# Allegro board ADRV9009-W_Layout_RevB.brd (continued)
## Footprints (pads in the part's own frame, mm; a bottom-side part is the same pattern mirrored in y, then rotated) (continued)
C0201
  rect 0.305x0.406 smd: 1(-0.318,0) 2(0.318,0)
C0402
  rect 0.61x0.61 smd: 1(-0.495,0) 2(0.495,0)
C0402#2
  rect 0.483x0.559 smd: 1(-0.438,0) 2(0.438,0)
C0603
  rect 1.092x1.194 smd: 1(-0.851,0) 2(0.851,0)
C0603#2
  rect 0.762x0.889 smd: 1(-0.7,0) 2(0.7,0)
C0805H53
  rect 1.295x1.6 smd: 1(-0.953,0) 2(0.953,0)
C0805H60
  rect 1.295x1.6 smd: 1(-0.953,0) 2(0.953,0)
C1210
  rect 1.575x2.692 smd: 1(-1.397,0) 2(1.397,0)
C1210-2
  rect 1.575x2.692 smd: 1(-1.397,0) 2(1.397,0)
C1210-2#2
  rect 1.092x2.057 smd: 1(-1.646,0) 2(1.646,0)
CNAMPHENOL132255-11
  rect 2.54x0.432 smd: 1(-0.508,0)
  rect 6.35x1.524 hole 0.508: 2(-2.413,4.25) 4(-2.413,-4.25)
  round 0.305 smd: 3(-2.413,4.25) 5(-2.413,-4.25)
CNBERG1X3H205LD36
  rect 1.651x1.651 hole 1.143: 1(0,0)
  round 1.651 hole 1.143: 2(2.54,0) 3(5.08,0)
CNBERG2X10H330LD36
  rect 1.651x1.651 hole 1.143: 1(0,0)
  round 1.651 hole 1.143: 2(0,2.54) 3(2.54,0) 4(2.54,2.54) 5(5.08,0) 6(5.08,2.54) 7(7.62,0) 8(7.62,2.54) 9(10.16,0) 10(10.16,2.54) 11(12.7,0) 12(12.7,2.54) 13(15.24,0) 14(15.24,2.54) 15(17.78,0) 16(17.78,2.54) 17(20.32,0) 18(20.32,2.54) 19(22.86,0) 20(22.86,2.54)
CNHDR2X10H251
  rect 0.737x2.794 smd: 1(-5.715,-2.032) 2(-5.715,2.032) 3(-4.445,-2.032) 4(-4.445,2.032) 5(-3.175,-2.032) 6(-3.175,2.032) 7(-1.905,-2.032) 8(-1.905,2.032) 9(-0.635,-2.032) 10(-0.635,2.032) 11(0.635,-2.032) 12(0.635,2.032) 13(1.905,-2.032) 14(1.905,2.032) 15(3.175,-2.032) 16(3.175,2.032) 17(4.445,-2.032) 18(4.445,2.032) 19(5.715,-2.032) 20(5.715,2.032)
CNHIROSE-U_FL-R-SMT-1
  rect 0.991x1.041 smd: 1(0,-1.521)
  rect 1.041x2.21 smd: 2(-1.471,0) 3(1.471,0)
CNJOHNSON142-0701-201
  round 2.032 hole 1.524: 1(0,0) 2(-2.54,2.54) 3(2.54,2.54) 4(2.54,-2.54) 5(-2.54,-2.54)
CNKEY5001TP
  round 1.524 hole 1.016: 1(0,0)
CNSAMTEC1X2H330LD36
  rect 1.651x1.651 hole 1.143: 1(-1.27,0)
  round 1.651 hole 1.143: 2(1.27,0)
CNSAMTEC2X5H338LD36
  rect 1.651x1.651 hole 1.143: 1(0,0)
  round 1.651 hole 1.143: 2(0,2.54) 3(2.54,0) 4(2.54,2.54) 5(5.08,0) 6(5.08,2.54) 7(7.62,0) 8(7.62,2.54) 9(10.16,0) 10(10.16,2.54)
CNSAMTECASP-134488-01
  round 2.54 hole 1.27 unplated: (-2.426,5.715) (51.956,8.763)
  round 0.889 smd: A1(0,0) A2(1.27,0) A3(2.54,0) A4(3.81,0) A5(5.08,0) A6(6.35,0) A7(7.62,0) A8(8.89,0) A9(10.16,0) A10(11.43,0) A11(12.7,0) A12(13.97,0) A13(15.24,0) A14(16.51,0) A15(17.78,0) A16(19.05,0) A17(20.32,0) A18(21.59,0) A19(22.86,0) A20(24.13,0) A21(25.4,0) A22(26.67,0) A23(27.94,0) A24(29.21,0) A25(30.48,0) A26(31.75,0) A27(33.02,0) A28(34.29,0) A29(35.56,0) A30(36.83,0) A31(38.1,0) A32(39.37,0) A33(40.64,0) A34(41.91,0) A35(43.18,0) A36(44.45,0) A37(45.72,0) A38(46.99,0) A39(48.26,0) A40(49.53,0) B1(0,1.27) B2(1.27,1.27) B3(2.54,1.27) B4(3.81,1.27) B5(5.08,1.27) B6(6.35,1.27) B7(7.62,1.27) B8(8.89,1.27) B9(10.16,1.27) B10(11.43,1.27) B11(12.7,1.27) B12(13.97,1.27) B13(15.24,1.27) B14(16.51,1.27) B15(17.78,1.27) B16(19.05,1.27) B17(20.32,1.27) B18(21.59,1.27) B19(22.86,1.27) B20(24.13,1.27) B21(25.4,1.27) B22(26.67,1.27) B23(27.94,1.27) B24(29.21,1.27) B25(30.48,1.27) B26(31.75,1.27) B27(33.02,1.27) B28(34.29,1.27) B29(35.56,1.27) B30(36.83,1.27) B31(38.1,1.27) B32(39.37,1.27) B33(40.64,1.27) B34(41.91,1.27) B35(43.18,1.27) B36(44.45,1.27) B37(45.72,1.27) B38(46.99,1.27) B39(48.26,1.27) B40(49.53,1.27) C1(0,2.54) C2(1.27,2.54) C3(2.54,2.54) C4(3.81,2.54) C5(5.08,2.54) C6(6.35,2.54) C7(7.62,2.54) C8(8.89,2.54) C9(10.16,2.54) C10(11.43,2.54) C11(12.7,2.54) C12(13.97,2.54) C13(15.24,2.54) C14(16.51,2.54) C15(17.78,2.54) C16(19.05,2.54) C17(20.32,2.54) C18(21.59,2.54) C19(22.86,2.54) C20(24.13,2.54) C21(25.4,2.54) C22(26.67,2.54) C23(27.94,2.54) C24(29.21,2.54) C25(30.48,2.54) C26(31.75,2.54) C27(33.02,2.54) C28(34.29,2.54) C29(35.56,2.54) C30(36.83,2.54) C31(38.1,2.54) C32(39.37,2.54) C33(40.64,2.54) C34(41.91,2.54) C35(43.18,2.54) C36(44.45,2.54) C37(45.72,2.54) C38(46.99,2.54) C39(48.26,2.54) C40(49.53,2.54) D1(0,3.81) D2(1.27,3.81) D3(2.54,3.81) D4(3.81,3.81) D5(5.08,3.81) D6(6.35,3.81) D7(7.62,3.81) D8(8.89,3.81) D9(10.16,3.81) D10(11.43,3.81) D11(12.7,3.81) D12(13.97,3.81) D13(15.24,3.81) D14(16.51,3.81) D15(17.78,3.81) D16(19.05,3.81) D17(20.32,3.81) D18(21.59,3.81) D19(22.86,3.81) D20(24.13,3.81) D21(25.4,3.81) D22(26.67,3.81) D23(27.94,3.81) D24(29.21,3.81) D25(30.48,3.81) D26(31.75,3.81) D27(33.02,3.81) D28(34.29,3.81) D29(35.56,3.81) D30(36.83,3.81) D31(38.1,3.81) D32(39.37,3.81) D33(40.64,3.81) D34(41.91,3.81) D35(43.18,3.81) D36(44.45,3.81) D37(45.72,3.81) D38(46.99,3.81) D39(48.26,3.81) D40(49.53,3.81) E1(0,5.08) E2(1.27,5.08) E3(2.54,5.08) E4(3.81,5.08) E5(5.08,5.08) E6(6.35,5.08) E7(7.62,5.08) E8(8.89,5.08) E9(10.16,5.08) E10(11.43,5.08) E11(12.7,5.08) E12(13.97,5.08) E13(15.24,5.08) E14(16.51,5.08) E15(17.78,5.08) E16(19.05,5.08) E17(20.32,5.08) E18(21.59,5.08) E19(22.86,5.08) E20(24.13,5.08) E21(25.4,5.08) E22(26.67,5.08) E23(27.94,5.08) E24(29.21,5.08) E25(30.48,5.08) E26(31.75,5.08) E27(33.02,5.08) E28(34.29,5.08) E29(35.56,5.08) E30(36.83,5.08) E31(38.1,5.08) E32(39.37,5.08) E33(40.64,5.08) E34(41.91,5.08) E35(43.18,5.08) E36(44.45,5.08) E37(45.72,5.08) E38(46.99,5.08) E39(48.26,5.08) E40(49.53,5.08) F1(0,6.35) F2(1.27,6.35) F3(2.54,6.35) F4(3.81,6.35) F5(5.08,6.35) F6(6.35,6.35) F7(7.62,6.35) F8(8.89,6.35) F9(10.16,6.35) F10(11.43,6.35) F11(12.7,6.35) F12(13.97,6.35) F13(15.24,6.35) F14(16.51,6.35) F15(17.78,6.35) F16(19.05,6.35) F17(20.32,6.35) F18(21.59,6.35) F19(22.86,6.35) F20(24.13,6.35) F21(25.4,6.35) F22(26.67,6.35) F23(27.94,6.35) F24(29.21,6.35) F25(30.48,6.35) F26(31.75,6.35) F27(33.02,6.35) F28(34.29,6.35) F29(35.56,6.35) F30(36.83,6.35) F31(38.1,6.35) F32(39.37,6.35) F33(40.64,6.35) F34(41.91,6.35) F35(43.18,6.35) F36(44.45,6.35) F37(45.72,6.35) F38(46.99,6.35) F39(48.26,6.35) F40(49.53,6.35) G1(0,7.62) G2(1.27,7.62) G3(2.54,7.62) G4(3.81,7.62) G5(5.08,7.62) G6(6.35,7.62) G7(7.62,7.62) G8(8.89,7.62) G9(10.16,7.62) G10(11.43,7.62) G11(12.7,7.62) G12(13.97,7.62) G13(15.24,7.62) G14(16.51,7.62) G15(17.78,7.62) G16(19.05,7.62) G17(20.32,7.62) G18(21.59,7.62) G19(22.86,7.62) G20(24.13,7.62) G21(25.4,7.62) G22(26.67,7.62) G23(27.94,7.62) G24(29.21,7.62) G25(30.48,7.62) G26(31.75,7.62) G27(33.02,7.62) G28(34.29,7.62) G29(35.56,7.62) G30(36.83,7.62) G31(38.1,7.62) G32(39.37,7.62) G33(40.64,7.62) G34(41.91,7.62) G35(43.18,7.62) G36(44.45,7.62) G37(45.72,7.62) G38(46.99,7.62) G39(48.26,7.62) G40(49.53,7.62) H1(0,8.89) H2(1.27,8.89) H3(2.54,8.89) H4(3.81,8.89) H5(5.08,8.89) H6(6.35,8.89) H7(7.62,8.89) H8(8.89,8.89) H9(10.16,8.89) H10(11.43,8.89) H11(12.7,8.89) H12(13.97,8.89) H13(15.24,8.89) H14(16.51,8.89) H15(17.78,8.89) H16(19.05,8.89) H17(20.32,8.89) H18(21.59,8.89) H19(22.86,8.89) H20(24.13,8.89) H21(25.4,8.89) H22(26.67,8.89) H23(27.94,8.89) H24(29.21,8.89) H25(30.48,8.89) H26(31.75,8.89) H27(33.02,8.89) H28(34.29,8.89) H29(35.56,8.89) H30(36.83,8.89) H31(38.1,8.89) H32(39.37,8.89) H33(40.64,8.89) H34(41.91,8.89) H35(43.18,8.89) H36(44.45,8.89) H37(45.72,8.89) H38(46.99,8.89) H39(48.26,8.89) H40(49.53,8.89) J1(0,10.16) J2(1.27,10.16) J3(2.54,10.16) J4(3.81,10.16) J5(5.08,10.16) J6(6.35,10.16) J7(7.62,10.16) J8(8.89,10.16) J9(10.16,10.16) J10(11.43,10.16) J11(12.7,10.16) J12(13.97,10.16) J13(15.24,10.16) J14(16.51,10.16) J15(17.78,10.16) J16(19.05,10.16) J17(20.32,10.16) J18(21.59,10.16) J19(22.86,10.16) J20(24.13,10.16) J21(25.4,10.16) J22(26.67,10.16) J23(27.94,10.16) J24(29.21,10.16) J25(30.48,10.16) J26(31.75,10.16) J27(33.02,10.16) J28(34.29,10.16) J29(35.56,10.16) J30(36.83,10.16) J31(38.1,10.16) J32(39.37,10.16) J33(40.64,10.16) J34(41.91,10.16) J35(43.18,10.16) J36(44.45,10.16) J37(45.72,10.16) J38(46.99,10.16) J39(48.26,10.16) J40(49.53,10.16) K1(0,11.43) K2(1.27,11.43) K3(2.54,11.43) K4(3.81,11.43) K5(5.08,11.43) K6(6.35,11.43) K7(7.62,11.43) K8(8.89,11.43) K9(10.16,11.43) K10(11.43,11.43) K11(12.7,11.43) K12(13.97,11.43) K13(15.24,11.43) K14(16.51,11.43) K15(17.78,11.43) K16(19.05,11.43) K17(20.32,11.43) K18(21.59,11.43) K19(22.86,11.43) K20(24.13,11.43) K21(25.4,11.43) K22(26.67,11.43) K23(27.94,11.43) K24(29.21,11.43) K25(30.48,11.43) K26(31.75,11.43) K27(33.02,11.43) K28(34.29,11.43) K29(35.56,11.43) K30(36.83,11.43) K31(38.1,11.43) K32(39.37,11.43) K33(40.64,11.43) K34(41.91,11.43) K35(43.18,11.43) K36(44.45,11.43) K37(45.72,11.43) K38(46.99,11.43) K39(48.26,11.43) K40(49.53,11.43)
CNSAMTECTSW-108-08-G-D-ST
  rect 1.651x1.651 hole 1.143: 1(0,0)
  round 1.651 hole 1.143: 2(0,2.54) 3(2.54,0) 4(2.54,2.54) 5(5.08,0) 6(5.08,2.54) 7(7.62,0) 8(7.62,2.54) 9(10.16,0) 10(10.16,2.54) 11(12.7,0) 12(12.7,2.54) 13(15.24,0) 14(15.24,2.54) 15(17.78,0) 16(17.78,2.54)
CNSMSMASQ276H379
  round 1.499 smd: 1(0,0)
  round 2.286 hole 1.778: 2(-2.54,-2.54) 3(2.54,-2.54) 4(2.54,2.54) 5(-2.54,2.54)
CNWIELAND3225
  rect 2.159x2.159 hole 1.651: 1(0,0)
  round 2.159 hole 1.651: 2(5,0)
DO214AA3
  rect 1.778x2.159 smd: A(2.032,0) C(-2.032,0)
ETC1
  rect 0.762x1.397 smd: 1(-1.27,1.714) 2(0,1.714) 3(1.27,1.714) 4(1.27,-1.714) 5(-1.27,-1.714)
F1206
  rect 1.143x2.032 smd: 1(-1.333,0) 2(1.333,0)
L0201
  rect 0.178x0.33 smd: 1(-0.203,0) 2(0.203,0)
L0402
  rect 0.889x0.813 smd: 1(-0.635,0) 2(0.635,0)
L0603
  rect 0.583x0.813 smd: 1(-0.737,0)
  rect 0.889x0.813 smd: 2(0.737,0)
L0805
  rect 1.143x1.27 smd: 1(-0.953,0) 2(0.953,0)
LED0603
  rect 0.965x0.762 smd: A(0.8,0) C(-0.8,0)
LED0603_A
  rect 0.889x0.787 smd: A(0.845,0) C(-0.845,0)
LSMSQ157H83
  rect 1.473x3.683 smd: 1(-1.232,0) 2(1.232,0)
LSMSQ157H122
  rect 0.965x3.708 smd: 1(-1.181,0) 2(1.181,0)
MSOP8_PAD2_16X1_73
  rect 0.33x1.575 smd: 1(-0.975,-2.171) 2(-0.325,-2.171) 3(0.325,-2.171) 4(0.975,-2.171) 5(0.975,2.171) 6(0.325,2.171) 7(-0.325,2.171) 8(-0.975,2.171)
  rect 2.159x1.727 smd: PAD(0,0)
POWERPAKSC70-6
  rect 0.305x0.33 smd: 1(-0.65,-0.91) 2(0,-0.91) 3(0.65,-0.91) 4(0.65,0.91) 5(0,0.91) 6(-0.65,0.91)
  rect 0.61x0.94 smd: PAD1(-0.465,0) PAD2(0.465,0)
QFN20_4X4_PAD2_6X2_6
  oval 0.305x1.041 smd: 1(-1,-2.019) 2(-0.5,-2.019) 3(0,-2.019) 4(0.5,-2.019) 5(1,-2.019) 11(1,2.019) 12(0.5,2.019) 13(0,2.019) 14(-0.5,2.019) 15(-1,2.019)
  oval 1.041x0.305 smd: 6(2.019,-1) 7(2.019,-0.5) 8(2.019,0) 9(2.019,0.5) 10(2.019,1) 16(-2.019,1) 17(-2.019,0.5) 18(-2.019,0) 19(-2.019,-0.5) 20(-2.019,-1)
  rect 2.591x2.591 smd: PAD(0,0)
QFN48_7X7_PAD5_6X5_6
  oval 0.305x0.94 smd: 1(-2.75,-3.5) 2(-2.25,-3.5) 3(-1.75,-3.5) 4(-1.25,-3.5) 5(-0.75,-3.5) 6(-0.25,-3.5) 7(0.25,-3.5) 8(0.75,-3.5) 9(1.25,-3.5) 10(1.75,-3.5) 11(2.25,-3.5) 12(2.75,-3.5) 25(2.75,3.5) 26(2.25,3.5) 27(1.75,3.5) 28(1.25,3.5) 29(0.75,3.5) 30(0.25,3.5) 31(-0.25,3.5) 32(-0.75,3.5) 33(-1.25,3.5) 34(-1.75,3.5) 35(-2.25,3.5) 36(-2.75,3.5)
  oval 0.94x0.305 smd: 13(3.5,-2.75) 14(3.5,-2.25) 15(3.5,-1.75) 16(3.5,-1.25) 17(3.5,-0.75) 18(3.5,-0.25) 19(3.5,0.25) 20(3.5,0.75) 21(3.5,1.25) 22(3.5,1.75) 23(3.5,2.25) 24(3.5,2.75) 37(-3.5,2.75) 38(-3.5,2.25) 39(-3.5,1.75) 40(-3.5,1.25) 41(-3.5,0.75) 42(-3.5,0.25) 43(-3.5,-0.25) 44(-3.5,-0.75) 45(-3.5,-1.25) 46(-3.5,-1.75) 47(-3.5,-2.25) 48(-3.5,-2.75)
  rect 5.588x5.588 smd: PAD(0,0)
QFN72_10X10_PAD5_3X5_3
  oval 0.305x0.838 smd: 1(-4.25,-4.95) 2(-3.75,-4.95) 3(-3.25,-4.95) 4(-2.75,-4.95) 5(-2.25,-4.95) 6(-1.75,-4.95) 7(-1.25,-4.95) 8(-0.75,-4.95) 9(-0.25,-4.95) 10(0.25,-4.95) 11(0.75,-4.95) 12(1.25,-4.95) 13(1.75,-4.95) 14(2.25,-4.95) 15(2.75,-4.95) 16(3.25,-4.95) 17(3.75,-4.95) 18(4.25,-4.95) 37(4.25,4.95) 38(3.75,4.95) 39(3.25,4.95) 40(2.75,4.95) 41(2.25,4.95) 42(1.75,4.95) 43(1.25,4.95) 44(0.75,4.95) 45(0.25,4.95) 46(-0.25,4.95) 47(-0.75,4.95) 48(-1.25,4.95) 49(-1.75,4.95) 50(-2.25,4.95) 51(-2.75,4.95) 52(-3.25,4.95) 53(-3.75,4.95) 54(-4.25,4.95)
  oval 0.838x0.305 smd: 19(4.95,-4.25) 20(4.95,-3.75) 21(4.95,-3.25) 22(4.95,-2.75) 23(4.95,-2.25) 24(4.95,-1.75) 25(4.95,-1.25) 26(4.95,-0.75) 27(4.95,-0.25) 28(4.95,0.25) 29(4.95,0.75) 30(4.95,1.25) 31(4.95,1.75) 32(4.95,2.25) 33(4.95,2.75) 34(4.95,3.25) 35(4.95,3.75) 36(4.95,4.25) 55(-4.95,4.25) 56(-4.95,3.75) 57(-4.95,3.25) 58(-4.95,2.75) 59(-4.95,2.25) 60(-4.95,1.75) 61(-4.95,1.25) 62(-4.95,0.75) 63(-4.95,0.25) 64(-4.95,-0.25) 65(-4.95,-0.75) 66(-4.95,-1.25) 67(-4.95,-1.75) 68(-4.95,-2.25) 69(-4.95,-2.75) 70(-4.95,-3.25) 71(-4.95,-3.75) 72(-4.95,-4.25)
  rect 5.994x5.994 smd: PAD(0,0)
R0201
  rect 0.305x0.406 smd: 1(-0.318,0) 2(0.318,0)
R0402
  rect 0.61x0.61 smd: 1(-0.495,0) 2(0.495,0)
R0603
  rect 1.092x1.194 smd: 1(-0.851,0) 2(0.851,0)
SC70
  rect 0.406x0.508 smd: 1(-0.65,-0.95) 2(0,-0.95) 3(0.65,-0.95) 4(0.65,0.95) 5(0,0.95) 6(-0.65,0.95)
SC70-6
  rect 0.406x0.508 smd: 1(-0.65,-0.95) 2(0,-0.95) 3(0.65,-0.95) 4(0.65,0.95) 5(0,0.95) 6(-0.65,0.95)
SO8
  rect 0.61x2.184 smd: 1(-1.905,-2.54) 2(-0.635,-2.54) 3(0.635,-2.54) 4(1.905,-2.54) 5(1.905,2.54) 6(0.635,2.54) 7(-0.635,2.54) 8(-1.905,2.54)
T0805_A
  rect 0.305x0.787 smd: 1(-0.65,-0.644) 2(0,-0.644) 3(0.65,-0.644) 4(0.65,0.644) 5(0,0.644) 6(-0.65,0.644)
TSML150W160H160
  rect 0.762x1.651 smd: 1(-1.27,1.587) 2(0,1.587) 3(1.27,1.587) 4(1.27,-1.587) 5(0,-1.587) 6(-1.27,-1.587)
TSSOP8
  rect 0.33x1.651 smd: 1(-0.975,-2.92) 2(-0.325,-2.92) 3(0.325,-2.92) 4(0.975,-2.92) 5(0.975,2.92) 6(0.325,2.92) 7(-0.325,2.92) 8(-0.975,2.92)
TSSOP14
  rect 0.432x1.778 smd: 1(-1.95,-2.92) 2(-1.3,-2.92) 3(-0.65,-2.92) 4(0,-2.92) 5(0.65,-2.92) 6(1.3,-2.92) 7(1.95,-2.92) 8(1.95,2.92) 9(1.3,2.92) 10(0.65,2.92) 11(0,2.92) 12(-0.65,2.92) 13(-1.3,2.92) 14(-1.95,2.92)
unnamed#2
  round 3.81 hole 2.54 unplated: (0,0)
US8
  rect 0.305x0.711 smd: 1(-0.75,-1.343) 2(-0.25,-1.343) 3(0.25,-1.343) 4(0.75,-1.343) 5(0.75,1.343) 6(0.25,1.343) 7(-0.25,1.343) 8(-0.75,1.343)
YSML276W197H71
  rect 1.803x2.007 smd: 1(-2.54,-2) 2(0,-2) 3(2.54,-2) 4(2.54,2) 5(0,2) 6(-2.54,2)
YSML555W358H240
  rect 1.27x2.54 smd: 1(-2.54,-4.064) 2(0,-4.064) 3(2.54,-4.064) 4(2.54,4.064) 5(0,4.064) 6(-2.54,4.064)

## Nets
AGND: C6.1 C101.2(N2) C102.2(N2) C121.2(N2) C122.2(N2) C123.2(N2) C124.2(N2) C125.2(N2) C126.2(N2) C127.2(N2) C128.2(N2) C129.2(N2) C130.2(N2) C131.2(N2) C132.2(N2) C133.2(N2) C134.2(N2) C135.2(N2) C136.2(N2) C137.2(N2) C201.2(N2) C203.2(N2) C208.2(N2) C210.2(N2) C215.2(N2) C217.2(N2) C222.2(N2) C224.2(N2) C240.1 C241.1 C242.1 C243.2(N2) C244.2(N2) C245.1 C246.2(N2) C247.1 C301.2(N2) C303.2(N2) C307.2(N2) C308.2(N2) C312.2(N2) C314.2(N2) C315.2(N2) C316.2(N2) C320.2(N2) C322.2(N2) C323.2(N2) C325.2(N2) C327.2(N2) C329.2(N2) C344.1 C345.1 C346.1 C347.1 C348.1 C349.1 C350.1 C351.1 C406.2(N2) C407.1 C408.2(N2) C414.1 C415.1 C417.2(N2) C418.2(N2) C421.1 C422.1 C423.1 C424.1 C425.2(N2) C426.2(N2) C427.1 C428.1 C429.1 C430.1 C431.1 C432.1 C433.1 C434.1 C435.1 C436.1 C437.1 C438.1 C439.1 C440.1 C441.1 C442.1 C443.1 C444.1 C601.2(N2) C602.2(N2) C603.2(N2) C604.2(N2) C605.2(N2) C606.2(N2) C607.2(N2) C608.2(N2) C609.2(N2) C610.2(N2) C611.2(N2) C612.2(N2) C613.2(N2) C614.2(N2) C615.2(N2) C616.2(N2) C617.2(N2) C618.2(N2) C619.2(N2) C620.2(N2) C621.2(N2) C622.2(N2) C623.2(N2) C624.2(N2) C625.2(N2) C626.2(N2) C627.2(N2) C628.2(N2) C629.2(N2) C630.2(N2) C631.2(N2) C632.2(N2) C633.2(N2) C634.2(N2) C635.2(N2) C636.2(N2) C637.2(N2) C638.2(N2) C639.2(N2) C640.2(N2) C641.2(N2) C642.2(N2) C643.2(N2) C701.1 C702.2(N2) C703.2(N2) C704.2(N2) C705.2(N2) C706.2(N2) C901.2(N2) C902.1 C903.1 C904.1 C905.2(N2) C906.1 C907.2(N2) C908.1 C909.2(N2) C910.1 C911.1 C912.1 C921.2(N2) C922.2(N2) C925.2(N2) C926.2(N2) C928.2(N2) C930.2(N2) C932.2(N2) C933.1 C934.1 C935.1 C936.2(N2) C937.1 C938.1 C939.2(N2) C940.1 C941.1 C942.2(N2) C943.2(N2) C944.2(N2) C945.2(N2) C946.2(N2) C947.2(N2) C948.2(N2) C949.2(N2) C950.2(N2) C951.2(N2) DS401.C DS402.C DS902.C J101.2 J101.3(SH2) J201.2 J201.3 J201.4 J201.5(SH4) J202.2 J202.3 J202.4 J202.5(SH4) J203.2 J203.3 J203.4 J203.5(SH4) J204.2 J204.3 J204.4 J204.5(SH4) J301.2 J301.3 J301.4 J301.5(SH4) J303.2 J303.3 J303.4 J303.5(SH4) J304.2 J304.3 J304.4 J304.5(SH4) J305.2 J305.3(SH2) J306.2 J306.3(SH2) J401.2 J401.3 J401.4 J401.5(SH4) J402.2 J402.3(SH2) J403.2 J403.3(SH2) J404.2 J404.3(SH2) J405.2 J405.3(SH2) J406.2 J406.3(SH2) J407.2 J407.3(SH2) J408.2 J408.3(SH2) J409.2 J409.3(SH2) J410.2 J410.3(SH2) J411.2 J411.3(SH2) J412.2 J412.3(SH2) J413.2 J413.3(SH2) P101.1 P101.2 P101.19 P101.20 P102.1 P102.2 P102.15 P102.16(N8) P103.1 P103.2 P104.1 P104.2 P701.3 P701.5 P701.9 P701.15 P701.19 P801.A1 P801.A4 P801.A5 P801.A8 P801.A9 P801.A12 P801.A13 P801.A16 P801.A17 P801.A20 P801.A21 P801.A24 P801.A25 P801.A28 P801.A29 P801.A32 P801.A33 P801.A36 P801.A37 P801.A40 P801.B2 P801.B3 P801.B6 P801.B7 P801.B10 P801.B11 P801.B14 P801.B15 P801.B18 P801.B19 P801.B22 P801.B23 P801.B26 P801.B27 P801.B30 P801.B31 P801.B34 P801.B35 P801.B38 P801.B39 P801.C1 P801.C4 P801.C5 P801.C8 P801.C9 P801.C12 P801.C13 P801.C16 P801.C17 P801.C20 P801.C21 P801.C24 P801.C25 P801.C28 P801.C29 P801.C32 P801.C33 P801.C36 P801.C38 P801.C40 P801.D2 P801.D3 P801.D6 P801.D7 P801.D10 P801.D13 P801.D16 P801.D19 P801.D22 P801.D25 P801.D28 P801.D37 P801.D39 P801.E1 P801.E4 P801.E5 P801.E8 P801.E11 P801.E14 P801.E17 P801.E20 P801.E23 P801.E26 P801.E29 P801.E32 P801.E35 P801.E38 P801.E40 P801.F2 P801.F3 P801.F6 P801.F9 P801.F12 P801.F15 P801.F18 P801.F21 P801.F24 P801.F27 P801.F30 P801.F33 P801.F36 P801.F39 P801.G1 P801.G4 P801.G5 P801.G8 P801.G11 P801.G14 P801.G17 P801.G20 P801.G23 P801.G26 P801.G29 P801.G32 P801.G35 P801.G38 P801.G40 P801.H3 P801.H6 P801.H9 P801.H12 P801.H15 P801.H18 P801.H21 P801.H24 P801.H27 P801.H30 P801.H33 P801.H36 P801.H39 P801.J1 P801.J4 P801.J5 P801.J8 P801.J11 P801.J14 P801.J17 P801.J20 P801.J23 P801.J26 P801.J29 P801.J32 P801.J35 P801.J38 P801.J40 P801.K2 P801.K3 P801.K6 P801.K9(N9) P801.K12 P801.K15 P801.K18 P801.K21 P801.K24 P801.K27 P801.K30 P801.K33 P801.K36 P801.K39 P901.2(N2) P903.2(N2) P904.2(N2) P905.2(N2) P906.2(N2) P907.2(N2) Q901.1 Q901.4(S2) R101.2(N2) R103.2(N2) R105.2(N2) R107.2(N2) R109.2(N2) R112.2(N2) R113.2(N2) R114.2(N2) R115.2(N2) R116.2(N2) R117.2(N2) R118.1 R118.2(N2) R401.1 R402.1 R403.2(N2) R404.1 R409.1 R414.2(N2) R441.1 R442.2(N2) R443.2(N2) R701.1 R711.1 R712.1 R713.1 R715.2(N2) R717.1 R719.1 R721.1 R723.1 R725.1 R727.1 R801.1 R901.1 R906.2(N2) R910.2(N2) R913.2(N2) R914.2(N2) R918.1 R919.1 R920.1 R924.1 R928.1 R932.2(N2) R933.2(N2) R934.2(N2) R937.2(N2) R940.1 T201.1 T202.1 T205.1 T207.1 T301.2 T301.5 T302.1 T303.1 TP602.1(N1) TP902.1(N1) TP904.1(N1) U101.A1 U101.A4 U101.A7 U101.A8 U101.A11 U101.A14 U101.B2 U101.B3 U101.B4 U101.B5 U101.B6 U101.B9 U101.B10 U101.B11 U101.B12 U101.B13 U101.B14 U101.C4 U101.C9 U101.C11 U101.D3 U101.D4 U101.D5 U101.D6 U101.D7 U101.D8 U101.D9 U101.D11 U101.D12 U101.E6 U101.E9 U101.F1 U101.F2 U101.F5 U101.F6 U101.F7 U101.F8 U101.F9 U101.F10 U101.F12 U101.F13 U101.F14 U101.G1 U101.G2 U101.G3 U101.G4 U101.G6 U101.G10 U101.G11 U101.G12 U101.G13 U101.G14 U101.H2 U101.H3 U101.H4 U101.H5 U101.H6 U101.H7 U101.H8 U101.H9 U101.H10 U101.H13 U101.J2 U101.J13 U101.K1 U101.K2 U101.K13 U101.K14 U101.L1 U101.L2 U101.L7 U101.L10(VSSD2) U101.M2 U101.M9 U101.N2 U101.N7 U101.N14 U101.P2 U101.P3 U101.P10 U102.4 U401.4 U401.9 U401.13 U401.PAD U402.4 U403.7 U404.3 U405.2 U702.4 U702.7(WC_N) U703.6 U703.9 U703.PAD U901.2 U901.3 U901.10 U901.11 U901.30 U901.PAD U902.4 U902.PAD Y401.3 Y402.3
VDD1P3_DIG: C640.1 C641.1 C642.1 C643.1 C927.1 C951.1 E902.2(N2) P904.1 R716.1 R923.2(N2) U101.L8 U101.L9
VDD_IF_LDO: C933.2(N2) R936.2(N2) U902.5 U902.7 U902.8
VDD_INTERFACE: C421.2(N2) C423.2(N2) C425.1 C934.2(N2) C935.2(N2) P701.1 P801.J39 P801.K40 P907.1 R102.1 R104.1 R106.1 R108.1 R110.1 R111.1 R718.1 R832.1 R833.1 R938.2(N2) R939.2(N2) U101.M12 U402.8 U403.1 U403.8 U404.1 U404.4 U902.1 U902.2(VOUT2)
VDDA1P3_ANLG: C601.1 C602.1 C924.1 C949.1 C950.1 E602.1 E611.1 E901.2(N2) P903.1 R601.1 R603.1 R604.1 R605.1 R606.1 R607.1 R608.1 R609.1 R610.1 R611.1 R726.1 R916.2(N2) TP601.1(N1)
VDDA1P3_AUX_SYNTH: C631.1 C632.1 C633.1 R610.2(N2) TP612.1(N1) U101.G8
VDDA1P3_AUX_VCO_LDO: C621.1 C622.1 C623.1 R607.2(N2) TP609.1(N1) U101.C10
VDDA1P3_BB: C603.1 C604.1 C605.1 R601.2(N2) TP603.1(N1) U101.E5
VDDA1P3_CLOCK_SYNTH: C616.1 C617.1 R605.2(N2) TP607.1(N1) U101.G5
VDDA1P3_CLOCK_VCO_LDO: C610.1 C611.1 C612.1 R603.2(N2) TP605.1(N1) U101.N1
VDDA1P3_DES: C637.1 C638.1 C639.1 R611.2(N2) TP614.1(N1) U101.N9 U101.P9
VDDA1P3_RF_LO: C624.1 C625.1 C626.1 C627.1 R613.2(N2) U101.C8
VDDA1P3_RF_SYNTH: C606.1 C607.1 C608.1 C609.1 E613.2(N2) U101.G7
VDDA1P3_RF_VCO_LDO: C628.1 C629.1 C630.1 R609.2(N2) TP611.1(N1) U101.C5 U101.C6
VDDA1P3_RX_RF: C613.1 C614.1 C615.1 L612.2(N2) R612.2(N2) U101.B1
VDDA1P3_RX_TX: C618.1 C619.1 C620.1 R606.2(N2) TP608.1(N1) U101.C3
VDDA1P3_SER: C634.1 C635.1 C636.1 E611.2(N2) TP613.1(N1) U101.N8 U101.P8
VDDA1P8_BB: C942.1 C943.1 C944.1 C945.1 R722.1 R942.2(N2) TP903.1(N1) U101.E4
VDDA1P8_TX: C307.1 C308.1 C315.1 C316.1 C946.1 C947.1 C948.1 E907.2(N2) L307.2(N2) L308.1 L315.2(N2) L316.1 R724.1 R941.2(N2) TP901.1(N1) U101.E12
VDDA_1P8: C931.1 C940.2(N2) C941.2(N2) E904.2(N2) E907.1 P906.1 R931.2(N2) R941.1 R942.1
VDDA_3P3: C135.1 C929.1 C936.1 C937.2(N2) E903.2(N2) E905.1 E906.1 P905.1 R119.1 R120.1 R720.1 R848.1 R927.2(N2) R935.1 R936.1 U101.C12 U102.8
1P3_BUCK_OUT: C916.2(N2) C925.1 C926.1 E902.1 L901.2(N2) R905.1 R922.2(N2)
3P3V_CLK1: C6.2(N2) C418.1 C422.2(N2) C424.2(N2) C426.1 C427.2(N2) C428.2(N2) C429.2(N2) C430.2(N2) C431.2(N2) C432.2(N2) C433.2(N2) C434.2(N2) C435.2(N2) C436.2(N2) C437.2(N2) C438.2(N2) C439.2(N2) C440.2(N2) C441.2(N2) C442.2(N2) C443.2(N2) C444.2(N2) E905.2(N2) R440.1 U401.1 U401.10 U401.16 U401.20 U401.27 U401.30 U401.33 U401.36 U401.39 U401.42 U401.45 U401.48 U401.51 U401.54 U401.60 U401.63 U401.66 U401.69 U401.72(VDD_5) U403.14 U404.6 U405.5
3P3V_VCXO: C407.2(N2) C938.2(N2) E906.2(N2) R408.1 Y401.6(VDD) Y402.6
3P3VAUX: C701.2(N2) C702.1 C703.1 C704.1 P801.D32 R708.2(N2) R709.2(N2) R710.2(N2) U702.8 U703.10 U703.16 U703.17
ADP5054_VREG: C902.2(N2) R903.2(N2) U901.13 U901.18 U901.44 U901.45(VREG)
AUX_SYNTH_OUT: U101.E10
AUX_SYNTH_VTUNE: J101.1 P104.6 U101.P1
AUXADC_0: C131.1 P103.3 U101.F3
AUXADC_1: C132.1 P103.4 U101.F4
AUXADC_2: C133.1 P103.5 U101.F11
AUXADC_3: C134.1 P103.6 U101.E11
CLK+: C403.2(N2) R406.1 U401.2
CLK-: C405.2(N2) R406.2(N2) U401.3
CLK_RESETB: R440.2(N2) U401.19 U404.5(Y)
CLK_SYSREF_REQUEST: R441.2(N2) U401.57 U403.13
DIR_CLK+: C402.2(N2) R416.2(N2)
DIR_CLK-: C404.2(N2) R415.2(N2)
EPROM_A0: P801.C34 R708.1 R711.2(N2) U702.1 U703.11
EPROM_A1: P801.D35 R709.1 R712.2(N2) U702.2 U703.13
EPROM_A2: R710.1 R713.2(N2) U702.3
FMC_CLK_RESETB: P801.D26 U404.2
FMC_SYSREF_REQUEST: P801.D27 U403.2
FMCA_SCL: P801.C30 U702.6 U703.15
FMCA_SDA: P801.C31 U702.5 U703.14
FMCA_VADJ: C932.1 P801.E39 P801.F40 P801.G39 P801.H40 R938.1 TP814.1(N1)
FMCA_VCC_3P3V: P801.C39 P801.D36 P801.D38 P801.D40 TP818.1(N1)
FMCA_VCC_12P0V: F901.1 P801.C35 P801.C37 TP819.1(N1)
FPGA_REF_CLK+: C801.1 C803.1 R420.2(N2) R422.2(N2)
FPGA_REF_CLK-: C802.1 C804.1 R419.2(N2) R421.2(N2)
FPGA_SYSREF+: R424.2(N2) R818.1
FPGA_SYSREF-: R425.2(N2) R819.1
FPGA_SYSREF_OUT+: R451.1 R834.1
FPGA_SYSREF_OUT-: R452.1 R835.1
GP_INTERRUPT: R805.1 TP804.1(N1) U101.J5
GPIO_0: P101.4 R108.2(N2) R109.1 R808.1 U101.K8
GPIO_1: P101.3 R106.2(N2) R107.1 R809.1 U101.J8
GPIO_2: P101.6 R104.2(N2) R105.1 R822.1 U101.J7
GPIO_3: P101.5 R102.2(N2) R103.1 R823.1 U101.K7
GPIO_3P3_0: C121.1 P102.3 U101.C1
GPIO_3P3_1: C122.1 P102.4 U101.D1
GPIO_3P3_2: P102.5 U101.E1
GPIO_3P3_3: P102.6 U101.C2
GPIO_3P3_4: C123.1 P102.7 U101.D2
GPIO_3P3_5: C124.1 P102.8 U101.E2
GPIO_3P3_6: C125.1 P102.9 U101.E3
GPIO_3P3_7: C126.1 P102.10 U101.E13
GPIO_3P3_8: C127.1 P102.11 U101.D13 U102.1
GPIO_3P3_9: C128.1 P102.12 U101.C13 U102.6
GPIO_3P3_10: C129.1 P102.13 U101.D14 U102.5
GPIO_3P3_11: C130.1 P102.14 U101.E14 U102.2
GPIO_4: P101.8 R707.2(N2) R812.1 U101.K6
GPIO_5: P101.7 R705.2(N2) R813.1 U101.K5
GPIO_6: P101.10 R706.2(N2) R843.1 U101.L5
GPIO_7: P101.9(N9) R702.2(N2) R844.1 U101.L6
GPIO_8: P101.12 R827.1 U101.L12
GPIO_9: P101.11 R810.1 U101.K12
GPIO_10: P101.14 R811.1 U101.J12
GPIO_11: P101.13 R824.1 U101.H12
GPIO_12: P101.16 R825.1 U101.H11
GPIO_13: P101.15 R831.1 U101.J11
GPIO_14: P101.18 R830.1 U101.K11
GPIO_15: P101.17 R826.1 U101.L11
GPIO_16: R817.1 U101.M11
GPIO_17: R816.1 U101.M10
GPIO_18: P104.4 R113.1 R704.2(N2) R837.1 U101.J3
INPUT_VOLTAGE: C901.1 C905.1 C907.1 C909.1 CR901.C DS901.A(P) R714.2(N2) R909.1 U901.6 U901.7 U901.22 U901.23 U901.24 U901.36 U901.37 U901.38
JTAG_TDI: P801.D30 R840.2(N2)
JTAG_TDO: P801.D31 R840.1
LDO_VCO_2P5: C416.1 C417.1 U401.15
LF_EXT_CAP: C414.2(N2) R439.2(N2) U401.7
LF_PLL2: C416.2(N2) U401.14
ORX1_BAL+: C218.2(N2) R220.1 T205.4
ORX1_BAL-: C218.1 R219.1 T205.5(SEC_DOT)
ORX1_IN+: C221.2(N2) R220.2(N2) U101.A12
ORX1_IN-: C221.1 R219.2(N2) U101.A13
ORX1_UNBAL: C217.1 C250.1 R216.2(N2)
ORX2_BAL+: C225.2(N2) R227.1 T207.4
ORX2_BAL-: C225.1 R226.1 T207.5(SEC_DOT)
ORX2_IN+: C228.2(N2) R227.2(N2) U101.A2
ORX2_IN-: C228.1 R226.2(N2) U101.A3
ORX2_UNBAL: C224.1 C251.1 R223.2(N2)
OUT1: R418.1 R420.1 U401.64
OUT1_N: R418.2(N2) R419.1 U401.65
OUT3: R423.2(N2) R424.1 U401.58
OUT3_N: R423.1 R425.1 U401.59
OUT5: C410.1 R426.1 U401.49
OUT5_N: C411.1 R426.2(N2) U401.50
OUT7: C412.1 R427.1 U401.43
OUT7_N: C413.1 R427.2(N2) U401.44
OUT8: R428.1 R429.1 U401.40
OUT8_N: R428.2(N2) R430.1 U401.41
OUT12: R431.2(N2) R432.1 U401.28
OUT12_N: R431.1 R433.1 U401.29
OUT13: R434.1 R436.1 U401.25
OUT13_N: R434.2(N2) R435.1 U401.26
PWRSUPPLYENABLE: P801.D1 R902.1
REF_CLK_IN+: C103.1 C445.2(N2) L401.1 R121.1 R436.2(N2) R438.1
REF_CLK_IN-: C104.1 C445.1 L401.2(N2) R121.2(N2) R435.2(N2) R437.1
RESETB: R110.2(N2) R804.1 TP803.1(N1) U101.J4
RF_EXT_LO+: C304.2(N2) U101.B8
RF_EXT_LO-: C305.2(N2) U101.B7
RF_SYNTH_VTUNE: C136.1 P104.5 U101.G9
RFO_1: C337.1 T302.3
RFO_2: C336.1 T303.3
RX1_BAL+: C204.1 R205.1 T201.5(SEC_DOT)
RX1_BAL-: C204.2(N2) R206.1 T201.4
RX1_ENABLE: P104.7 R117.1 R839.1 U101.M5
RX1_IN+: C207.1 R205.2(N2) U101.A9
RX1_IN-: C207.2(N2) R206.2(N2) U101.A10
RX1_UNBAL: C203.1 C248.1 R202.2(N2)
RX2_BAL+: C211.1 R212.1 T202.5(SEC_DOT)
RX2_BAL-: C211.2(N2) R213.1 T202.4
RX2_ENABLE: P104.8 R116.1 R842.1 U101.M7
RX2_IN+: C214.1 R212.2(N2) U101.A5
RX2_IN-: C214.2(N2) R213.2(N2) U101.A6
RX2_UNBAL: C210.1 C249.1 R209.2(N2)
SERDIN0+: C113.1 P801.A22
SERDIN0-: C114.1 P801.A23
SERDIN1+: C115.1 P801.A30
SERDIN1-: C116.1 P801.A31
SERDIN2+: C117.1 P801.C2
SERDIN2-: C118.1 P801.C3
SERDIN3+: C119.1 P801.A26
SERDIN3-: C120.1 P801.A27
SERDOUT0+: C105.1 P801.A2
SERDOUT0-: C106.1 P801.A3
SERDOUT1+: C107.1 P801.A6
SERDOUT1-: C108.1 P801.A7
SERDOUT2+: C109.1 P801.C6
SERDOUT2-: C110.1 P801.C7
SERDOUT3+: C111.1 P801.A10
SERDOUT3-: C112.1 P801.A11
SPI_CLK: R806.1 TP805.1(N1) U101.K9 U403.3
SPI_CLK_9528: U401.22 U403.12
SPI_CS0: R832.2(N2) R846.1 TP816.1(N1) U101.K10 U402.7
SPI_CS1: R833.2(N2) R847.1 TP815.1(N1) U402.1 U403.5
SPI_CS_9528: U401.21 U403.10(Y4)
SPI_DIN: R807.1 TP806.1(N1) U101.J9 U403.4
SPI_DIN_9528: U401.23 U403.11
SPI_DOUT: R845.1 TP811.1(N1) U402.3(Y2) U402.6
SPI_DOUT_9528: R453.2(N2) TP400.1(N1) U401.24
SPI_DOUT_DUT: R454.2(N2) TP401.1(N1) U101.J10
STATUS_0: R442.1 R444.1 U401.55
STATUS_1: R443.1 R445.1 U401.56
SYNCINB0+: R820.1 TP809.1(N1) U101.M4
SYNCINB0-: R821.1 TP810.1(N1) U101.M3
SYNCINB1+: R828.1 TP812.1(N1) U101.L4
SYNCINB1-: R829.1 TP813.1(N1) U101.L3
SYNCOUTB0+: R802.1 TP801.1(N1) U101.M14
SYNCOUTB0-: R803.1 TP802.1(N1) U101.M13
SYNCOUTB1+: R814.1 TP807.1(N1) U101.L14
SYNCOUTB1-: R815.1 TP808.1(N1) U101.L13
SYSREF_CLK_IN+: C419.2(N2) R451.2(N2) U401.70
SYSREF_CLK_IN-: C420.2(N2) R452.2(N2) U401.71
SYSREF_IN+: R432.2(N2) U101.K3
SYSREF_IN-: R433.2(N2) U101.K4
TEST: R111.2(N2) R112.1 R836.1 TP817.1(N1) U101.J6
TX1_BAL+: C338.1 R307.2(N2) T302.5(SEC_DOT)
TX1_BAL-: C338.2(N2) R308.2(N2) T302.4
TX1_ENABLE: P104.9(N9) R115.1 R838.1 U101.M6
TX1_OUT+: C339.1 L307.1 L323.1 R307.1 U101.H14
TX1_OUT-: C339.2(N2) L308.2(N2) L325.1 R308.1 U101.J14
TX2_BAL+: C342.1 R310.2(N2) T303.5(SEC_DOT)
TX2_BAL-: C342.2(N2) R311.2(N2) T303.4
TX2_ENABLE: P104.10 R114.1 R841.1 U101.M8
TX2_OUT+: C341.1 L315.1 L327.1 R310.1 U101.J1
TX2_OUT-: C341.2(N2) L316.2(N2) L329.1 R311.1 U101.H1
UNNAMED_2_ADRV9009_I127_RBIAS: R101.1 U101.C14
UNNAMED_2_ADRV9009_I127_VDDA1_1: C101.1 U101.M1
UNNAMED_2_ADRV9009_I127_VDDA1_2: C102.1 U101.C7
UNNAMED_2_ADRV9009_I127_VDDA1P1: C137.1 U101.D10
UNNAMED_2_CAP_I88_N2: C103.2(N2) U101.E7
UNNAMED_2_CAP_I89_N2: C104.2(N2) U101.E8
UNNAMED_2_CAP_I91_N2: C105.2(N2) U101.P7
UNNAMED_2_CAP_I92_N2: C106.2(N2) U101.P6
UNNAMED_2_CAP_I93_N2: C108.2(N2) U101.P4
UNNAMED_2_CAP_I94_N2: C107.2(N2) U101.P5
UNNAMED_2_CAP_I95_N2: C112.2(N2) U101.N3
UNNAMED_2_CAP_I96_N2: C109.2(N2) U101.N6
UNNAMED_2_CAP_I97_N2: C110.2(N2) U101.N5
UNNAMED_2_CAP_I98_N2: C111.2(N2) U101.N4
UNNAMED_2_CAP_I99_N2: C114.2(N2) U101.N12
UNNAMED_2_CAP_I100_N2: C113.2(N2) U101.N13
UNNAMED_2_CAP_I101_N2: C116.2(N2) U101.N10
UNNAMED_2_CAP_I102_N2: C118.2(N2) U101.P13
UNNAMED_2_CAP_I103_N2: C115.2(N2) U101.N11
UNNAMED_2_CAP_I104_N2: C117.2(N2) U101.P14
UNNAMED_2_CAP_I105_N2: C120.2(N2) U101.P11
UNNAMED_2_CAP_I106_N2: C119.2(N2) U101.P12
UNNAMED_2_ICS25FL208K_I27_HOLDN: R119.2(N2) U102.7
UNNAMED_2_ICS25FL208K_I27_WPN: R120.2(N2) U102.3(WP_N)
UNNAMED_3_CAP_I159_N1: C201.1 J201.1 R202.1
UNNAMED_3_CAP_I180_N1: C208.1 J202.1 R209.1
UNNAMED_3_CAP_I206_N1: C222.1 J204.1 R223.1
UNNAMED_3_CAP_I230_N1: C215.1 J203.1 R216.1
UNNAMED_3_CAP_I241_N2: C240.2(N2) C241.2(N2) T201.2
UNNAMED_3_CAP_I245_N1: C242.2(N2) C243.1 T202.2
UNNAMED_3_CAP_I248_N1: C244.1 C245.2(N2) T205.2
UNNAMED_3_CAP_I252_N1: C246.1 C247.2(N2) T207.2
UNNAMED_3_CAP_I256_N2: C248.2(N2) T201.3
UNNAMED_3_CAP_I257_N2: C249.2(N2) T202.3
UNNAMED_3_CAP_I258_N2: C251.2(N2) T207.3
UNNAMED_3_CAP_I259_N2: C250.2(N2) T205.3
UNNAMED_4_CAP_I166_N1: C404.1 C405.1 R404.2(N2) R405.2(N2) T401.3
UNNAMED_4_CAP_I168_N1: C401.1 J401.1 R401.2(N2)
UNNAMED_4_CAP_I168_N2: C401.2(N2) T401.4
UNNAMED_4_CAP_I177_N1: C402.1 C403.1 R403.1 R405.1 T401.1
UNNAMED_4_CAP_I184_N1: C409.1 R413.1 R417.2(N2)
UNNAMED_4_CAP_I192_N2: C415.2(N2) R439.1
UNNAMED_4_CAP_I274_N1: C408.1 R412.1 R413.2(N2) R414.1
UNNAMED_4_CAP_I292_N2: C411.2(N2) J405.1
UNNAMED_4_CAP_I294_N2: C410.2(N2) J404.1
UNNAMED_4_CAP_I303_N2: C413.2(N2) J407.1
UNNAMED_4_CAP_I304_N2: C412.2(N2) J406.1
UNNAMED_4_CAP_I329_N1: C420.1 R449.2(N2) R450.2(N2)
UNNAMED_4_CAP_I330_N1: C419.1 R448.2(N2) R450.1
UNNAMED_4_CMOSNC7WV125K8X_I27_1: R454.1 U402.5
UNNAMED_4_CMOSNC7WV125K8X_I279_: R453.1 U402.2
UNNAMED_4_CNBNC3P_I148_CNTR: J411.1 R438.2(N2)
UNNAMED_4_CNBNC3P_I248_CNTR: J410.1 R437.2(N2)
UNNAMED_4_CNBNC3P_I306_CNTR: J409.1 R430.2(N2)
UNNAMED_4_CNBNC3P_I308_CNTR: J408.1 R429.2(N2)
UNNAMED_4_CNBNC3P_I318_CNTR: J403.1 R422.1
UNNAMED_4_CNBNC3P_I321_CNTR: J402.1 R421.1
UNNAMED_4_CNBNC3P_I324_CNTR: J412.1 R448.1
UNNAMED_4_CNBNC3P_I325_CNTR: J413.1 R449.1
UNNAMED_4_CNTP1P_I73_N1: R444.2(N2) TP403.1(N1) U405.1
UNNAMED_4_CNTP1P_I74_N1: R445.2(N2) TP402.1(N1) U405.3
UNNAMED_4_DIOLED_I333_P: DS401.A(P) R446.2(N2)
UNNAMED_4_DIOLED_I334_P: DS402.A(P) R447.2(N2)
UNNAMED_4_NC7WZ17P6X_I76_Y1: R446.1 U405.6
UNNAMED_4_NC7WZ17P6X_I76_Y2: R447.1 U405.4(Y2)
UNNAMED_4_RES_I165_N2: R410.2(N2) R411.1 R412.2(N2)
UNNAMED_4_RES_I268_N2: R402.2(N2) T401.5(N4)
UNNAMED_5_CNTP1P_I268_N1: E602.2(N2) E613.1 TP604.1(N1)
UNNAMED_5_RES_I164_N2: R608.2(N2) R613.1 TP610.1(N1)
UNNAMED_5_RES_I174_N2: L612.1 R604.2(N2) R612.1 TP606.1(N1)
UNNAMED_7_CAP_I11_N2: C802.2(N2) P801.D5
UNNAMED_7_CAP_I12_N2: C801.2(N2) P801.D4
UNNAMED_7_CAP_I157_N2: C803.2(N2) P801.B20
UNNAMED_7_CAP_I158_N2: C804.2(N2) P801.B21
UNNAMED_7_CN400PAK_I2_N8: P801.D8 R834.2(N2)
UNNAMED_7_CN400PAK_I2_N9: P801.D9 R835.2(N2)
UNNAMED_7_CN400PAK_I2_N14: P801.D14 R846.2(N2)
UNNAMED_7_CN400PAK_I2_N15: P801.D15 R847.2(N2)
UNNAMED_7_CN400PAK_I2_N17: P801.D17 R838.2(N2)
UNNAMED_7_CN400PAK_I2_N18: P801.D18 R839.2(N2)
UNNAMED_7_CN400PAK_I27_N10: P801.C10 R816.2(N2)
UNNAMED_7_CN400PAK_I27_N11: P801.C11 R817.2(N2)
UNNAMED_7_CN400PAK_I27_N18: P801.C18 R841.2(N2)
UNNAMED_7_CN400PAK_I27_N19: P801.C19 R842.2(N2)
UNNAMED_7_CN400PAK_I27_N22: P801.C22 R843.2(N2)
UNNAMED_7_CN400PAK_I27_N23: P801.C23 R844.2(N2)
UNNAMED_7_CN400PAK_I52_N2: P801.H2 R801.2(N2)
UNNAMED_7_CN400PAK_I52_N7: P801.H7 R802.2(N2)
UNNAMED_7_CN400PAK_I52_N8: P801.H8 R803.2(N2)
UNNAMED_7_CN400PAK_I52_N10: P801.H10 R804.2(N2)
UNNAMED_7_CN400PAK_I52_N11: P801.H11 R805.2(N2)
UNNAMED_7_CN400PAK_I52_N13: P801.H13 R806.2(N2)
UNNAMED_7_CN400PAK_I52_N14: P801.H14 R807.2(N2)
UNNAMED_7_CN400PAK_I52_N16: P801.H16 R836.2(N2)
UNNAMED_7_CN400PAK_I52_N17: P801.H17 R837.2(N2)
UNNAMED_7_CN400PAK_I52_N19: P801.H19 R808.2(N2)
UNNAMED_7_CN400PAK_I52_N20: P801.H20 R809.2(N2)
UNNAMED_7_CN400PAK_I52_N22: P801.H22 R810.2(N2)
UNNAMED_7_CN400PAK_I52_N23: P801.H23 R811.2(N2)
UNNAMED_7_CN400PAK_I52_N25: P801.H25 R812.2(N2)
UNNAMED_7_CN400PAK_I52_N26: P801.H26 R813.2(N2)
UNNAMED_7_CN400PAK_I52_N28: P801.H28 R814.2(N2)
UNNAMED_7_CN400PAK_I52_N29: P801.H29 R815.2(N2)
UNNAMED_7_CN400PAK_I55_N6: P801.G6 R818.2(N2)
UNNAMED_7_CN400PAK_I55_N7: P801.G7 R819.2(N2)
UNNAMED_7_CN400PAK_I55_N9: P801.G9 R820.2(N2)
UNNAMED_7_CN400PAK_I55_N10: P801.G10 R821.2(N2)
UNNAMED_7_CN400PAK_I55_N12: P801.G12 R845.2(N2)
UNNAMED_7_CN400PAK_I55_N15: P801.G15 R830.2(N2)
UNNAMED_7_CN400PAK_I55_N16: P801.G16 R831.2(N2)
UNNAMED_7_CN400PAK_I55_N18: P801.G18 R822.2(N2)
UNNAMED_7_CN400PAK_I55_N19: P801.G19 R823.2(N2)
UNNAMED_7_CN400PAK_I55_N21: P801.G21 R824.2(N2)
UNNAMED_7_CN400PAK_I55_N22: P801.G22 R825.2(N2)
UNNAMED_7_CN400PAK_I55_N24: P801.G24 R826.2(N2)
UNNAMED_7_CN400PAK_I55_N25: P801.G25 R827.2(N2)
UNNAMED_7_CN400PAK_I55_N27: P801.G27 R828.2(N2)
UNNAMED_7_CN400PAK_I55_N28: P801.G28 R829.2(N2)
UNNAMED_7_CN400PAK_I67_N1: P801.F1 R848.2(N2)
UNNAMED_9_AD7291_I112_DCAP: C706.1 U703.8
UNNAMED_9_AD7291_I112_VIN0: R714.1 R715.1 U703.18
UNNAMED_9_AD7291_I112_VIN1: R716.2(N2) R717.2(N2) U703.19
UNNAMED_9_AD7291_I112_VIN2: R718.2(N2) R719.2(N2) U703.20
UNNAMED_9_AD7291_I112_VIN3: R720.2(N2) R721.2(N2) U703.1
UNNAMED_9_AD7291_I112_VIN4: R722.2(N2) R723.2(N2) U703.2
UNNAMED_9_AD7291_I112_VIN5: R724.2(N2) R725.2(N2) U703.3
UNNAMED_9_AD7291_I112_VIN7: R726.2(N2) R727.2(N2) U703.5
UNNAMED_9_AD7291_I112_VREF: C705.1 U703.7(VREF)
UNNAMED_9_CN20PV2_I59_N1: P701.2 R702.1
UNNAMED_9_CN20PV2_I59_N2: P701.4 R704.1
UNNAMED_9_CN20PV2_I59_N3: P701.6 R705.1
UNNAMED_9_CN20PV2_I59_N4: P701.8 R706.1
UNNAMED_9_CN20PV2_I59_N8: P701.16 R707.1
UNNAMED_9_CN20PV2_I60_N6: P701.11 TP702.1(N1)
UNNAMED_9_CN20PV2_I60_N7: P701.13 TP701.1(N1)
UNNAMED_9_CN20PV2_I60_N9: P701.17 R701.2(N2)
UNNAMED_10_CAP_I10_N1: C305.1 R305.2(N2) T301.4
UNNAMED_10_CAP_I11_N1: C304.1 R304.2(N2) T301.3
UNNAMED_10_CAP_I51_N1: C314.1 J303.1 R309.2(N2)
UNNAMED_10_CAP_I60_N1: C322.1 J304.1 R312.2(N2)
UNNAMED_10_CAP_I118_N1: C301.1 J301.1 R302.1
UNNAMED_10_CAP_I121_N1: C303.1 R302.2(N2) T301.1(UNBAL)
UNNAMED_10_CAP_I142_N1: C323.1 L323.2(N2)
UNNAMED_10_CAP_I145_N1: C325.1 L325.2(N2)
UNNAMED_10_CAP_I148_N1: C327.1 L327.2(N2)
UNNAMED_10_CAP_I152_N1: C329.1 L329.2(N2)
UNNAMED_10_CAP_I156_N2: C320.1 C336.2(N2) R312.1
UNNAMED_10_CAP_I157_N2: C312.1 C337.2(N2) R309.1
UNNAMED_10_CAP_I181_N2: C344.2(N2) C345.2(N2) C346.2(N2) C347.2(N2) T302.2
UNNAMED_10_CAP_I188_N2: C348.2(N2) C349.2(N2) C350.2(N2) C351.2(N2) T303.2
UNNAMED_10_CNBNC3P_I129_CNTR: J305.1 R304.1
UNNAMED_10_CNBNC3P_I130_CNTR: J306.1 R305.1
UNNAMED_11_ADP125_I130_ADJ: R939.1 R940.2(N2) U902.3
UNNAMED_11_ADP5054_I29_BST1: C913.1 U901.32
UNNAMED_11_ADP5054_I29_BST2: C915.2(N2) U901.28
UNNAMED_11_ADP5054_I29_BST3: C917.1 U901.1
UNNAMED_11_ADP5054_I29_BST4: C919.1 U901.12
UNNAMED_11_ADP5054_I29_COMP1: R904.2(N2) U901.40
UNNAMED_11_ADP5054_I29_COMP2: R907.2(N2) U901.20
UNNAMED_11_ADP5054_I29_COMP3: R908.2(N2) U901.47
UNNAMED_11_ADP5054_I29_COMP4: R911.2(N2) U901.15
UNNAMED_11_ADP5054_I29_DL1: Q901.5 R918.2(N2) U901.31
UNNAMED_11_ADP5054_I29_DL2: Q901.2 R919.2(N2) U901.29
UNNAMED_11_ADP5054_I29_EN1: C911.2(N2) P902.2 R905.2(N2) R906.1 U901.14 U901.39
UNNAMED_11_ADP5054_I29_EN2: P902.1 R902.2(N2) R903.1 U901.21
UNNAMED_11_ADP5054_I29_EN3: C912.2(N2) P902.3(N3) R909.2(N2) R910.1 R912.1 U901.48
UNNAMED_11_ADP5054_I29_FB1: R914.1 R915.1 R916.1 R917.1 U901.41
UNNAMED_11_ADP5054_I29_FB2: R920.2(N2) R921.1 R922.1 R923.1 U901.19
UNNAMED_11_ADP5054_I29_FB3: R924.2(N2) R925.1 R926.1 R927.1 U901.46
UNNAMED_11_ADP5054_I29_FB4: R928.2(N2) R929.1 R930.1 R931.1 U901.16
UNNAMED_11_ADP5054_I29_PWRGD: R912.2(N2) U901.17
UNNAMED_11_ADP5054_I29_RT: R913.1 U901.42
UNNAMED_11_ADP5054_I29_SW11: C913.2(N2) L900.1 Q901.3 Q901.PAD2 U901.33 U901.34 U901.35
UNNAMED_11_ADP5054_I29_SW21: C915.1 L901.1 Q901.6 Q901.PAD1 U901.25 U901.26 U901.27
UNNAMED_11_ADP5054_I29_SW31: C917.2(N2) L902.1 U901.4 U901.5
UNNAMED_11_ADP5054_I29_SW41: C919.2(N2) L903.1 U901.8 U901.9
UNNAMED_11_ADP5054_I29_VDD: C903.2(N2) U901.43
UNNAMED_11_CAP_I25_N2: C910.2(N2) R911.1
UNNAMED_11_CAP_I27_N2: C908.2(N2) R908.1
UNNAMED_11_CAP_I30_N2: C906.2(N2) R907.1
UNNAMED_11_CAP_I32_N2: C904.2(N2) R904.1
UNNAMED_11_CAP_I54_N1: C920.1 R929.2(N2)
UNNAMED_11_CAP_I54_N2: C920.2(N2) C930.1 E904.1 L903.2(N2) R930.2(N2)
UNNAMED_11_CAP_I55_N1: C918.1 R925.2(N2)
UNNAMED_11_CAP_I55_N2: C918.2(N2) C928.1 C939.1 E903.1 L902.2(N2) R926.2(N2)
UNNAMED_11_CAP_I56_N1: C916.1 R921.2(N2)
UNNAMED_11_CAP_I59_N1: C914.1 R915.2(N2)
UNNAMED_11_CAP_I59_N2: C914.2(N2) C921.1 C922.1 E901.1 L900.2(N2) R917.2(N2)
UNNAMED_11_CAP_I80_N2: C931.2(N2) R937.1
UNNAMED_11_CAP_I84_N2: C929.2(N2) R934.1
UNNAMED_11_CAP_I93_N2: C927.2(N2) R933.1
UNNAMED_11_CAP_I103_N2: C924.2(N2) R932.1
UNNAMED_11_CN2P_I1_N1: F902.1 P901.1
UNNAMED_11_DIO_I7_P: CR901.A(P) F901.2(N2) F902.2(N2)
UNNAMED_11_DIOLED_I8_N: DS901.C R901.2(N2)
UNNAMED_11_DIOLED_I179_P: DS902.A(P) R935.2(N2)
VCXO_CON: C406.1 R407.2(N2) Y401.1 Y402.1(VCNTRL)
VCXO_CTRL: R407.1 U401.8
VCXO_EN: R408.2(N2) R409.2(N2) Y401.2 Y402.2
VCXO_IN+: C409.2(N2) R416.1 U401.11
VCXO_IN-: R411.2(N2) R415.1 U401.12
VCXO_OUT+: R410.1 Y401.4 Y402.4
VCXO_OUT-: R417.1 Y401.5 Y402.5

Pads without a net: P103 7 8 9 10; P104 3; P701 7 10 12 14 18 20; P801 A14 A15 A18 A19 A34 A35 A38 A39 B1 B4 B5 B8 B9 B12 B13 B16 B17 B24 B25 B28 B29 B32 B33 B36 B37 B40 C14 C15 C26 C27 D11 D12 D20 D21 D23 D24 D29 D33 D34 E2 E3 E6 E7 E9 E10 E12 E13 E15 E16 E18 E19 E21 E22 E24 E25 E27 E28 E30 E31 E33 E34 E36 E37 F4 F5 F7 F8 F10 F11 F13 F14 F16 F17 F19 F20 F22 F23 F25 F26 F28 F29 F31 F32 F34 F35 F37 F38 G2 G3 G13 G30 G31 G33 G34 G36 G37 H1 H4 H5 H31 H32 H34 H35 H37 H38 J2 J3 J6 J7 J9 J10 J12 J13 J15 J16 J18 J19 J21 J22 J24 J25 J27 J28 J30 J31 J33 J34 J36 J37 K1 K4 K5 K7 K8 K10 K11 K13 K14 K16 K17 K19 K20 K22 K23 K25 K26 K28 K29 K31 K32 K34 K35 K37 K38; T201 6; T202 6; T205 6; T207 6; T301 6; T302 6; T303 6; T401 2; U401 5 6 17 18 31 32 34 35 37 38 46 47 52 53 61 62 67 68; U403 6 9; U703 4 12; U902 6

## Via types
v1: diameter 0.406, hole 0.203, TOP to BOTTOM, 276 vias
v2: diameter 0.508, hole 0.254, TOP to BOTTOM, 1052 vias
v3: diameter 0.305, hole 0.153, TOP to L10_SIG, 109 vias
v4: diameter 0.508, hole 0.254, TOP to L10_SIG, 106 vias
v5: diameter 0.305, hole 0.152, TOP to BOTTOM, 101 vias
v6: diameter 0.508, hole 0.255, L11_GND to BOTTOM, 136 vias
v7: diameter 0.406, hole 0.203, L11_GND to BOTTOM, 14 vias
v8: diameter 1.016, hole 0.508, TOP to BOTTOM, 13 vias

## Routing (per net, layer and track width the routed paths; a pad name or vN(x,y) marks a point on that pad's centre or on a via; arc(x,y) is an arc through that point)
AGND: length 2456.3
  TOP w0.127: 36.89,15.68 36.94,15.68 ; R118.1 R118.2 ; 32.73,52.47 32.78,52.47
  TOP w0.254: C315.2 38.3,24.68 ; R103.2 91.95,42.71 v2(92.01,42.65) ; U101.H6 v3(34.04,32.48) ; v5(33.24,28.48) U101.G1 v5(34.04,29.28) ; v5(34.84,36.48) U101.H10 ; v5(29.24,36.48) U101.B11 v5(29.24,37.28) U101.B12 v5(29.24,38.08) U101.B13 v5(29.24,38.88) U101.A14 v5(28.44,39.68) ; v5(29.24,36.48) U101.A11 v4(28.23,36.82) ; v5(29.24,36.48) U101.B10 v3(29.24,35.68) U101.B9 ; C347.1 32.7,53.37 ; v5(28.44,31.68) U101.A4 v5(29.24,30.88) ; U101.L2 v5(36.44,29.28) ; v5(36.44,29.28) U101.L1 ; v5(36.44,29.28) U101.K2 v5(35.64,29.28) ; v5(36.44,29.28) U101.K1 ; 13.85,37.5 14.04,37.7 C241.1 ; U101.F13 v3(32.44,38.88) ; C440.1 106.12,66.77 v2(105.47,66.77) ; R712.1 115.82,18.31 v2(115.86,18.28) ; 49.05,66.41 49.11,66.35 R701.1 ; v5(37.24,36.48) U101.L10 ; C327.2 36.78,23.92 ; v2(121.08,22.86) 121.53,22.41 U404.3 ; U101.N14 v3(38.84,39.68) ; 36.78,44.24 C325.2 ; v5(34.84,35.68) U101.H9 ; U101.G13 v5(34.04,38.88) ; v5(34.04,38.88) U101.G14 33.19,39.73 v3(33.19,39.89) ; v5(34.04,38.88) U101.H13 v5(34.84,38.88) U101.J13 v5(35.64,38.88) ; U101.L7 v3(37.24,33.28) ; U101.C11 v3(30.04,37.28) ; v5(34.84,30.08) U101.H3 ; 36.91,15.67 36.89,15.68 C348.1 ; U101.D8 v5(30.84,34.88) ; v5(34.04,37.28) U101.G11 ; v5(34.04,29.28) U101.H2 v5(34.84,29.28) U101.J2 v5(35.64,29.28) ; v5(34.04,29.28) U101.G2 33.24,29.28 v5(33.21,29.28) ; v5(34.84,34.92) 34.84,34.88 U101.H8 ; v5(29.24,30.88) U101.B4 v5(29.24,31.68) U101.B5 v3(29.24,32.48) U101.B6 ; v5(29.24,30.88) U101.B3 v5(29.24,30.08) U101.B2 v5(29.24,29.28) U101.A1 v5(28.44,28.48) ; U101.F12 v3(33.24,38.08) ; v5(33.24,31.68) U101.F5 ; v5(39.61,36.41) 39.57,36.41 U101.P10 ; U101.E9 v3(31.64,35.68) ; R901.1 v2(124.94,2.82) ; 32.64,55.03 32.77,55.16 32.9,55.16 ; v5(38.84,29.28) U101.N2 ; v5(38.04,35.68) U101.M9 ; v5(33.24,35.68) U101.F9 ; U101.P2 v5(39.64,29.28) ; C349.1 36.97,14.78 ; U101.H5 v3(34.84,32.48) ; v5(33.24,34.08) U101.F7 ; U101.F1 v3(32.44,28.48) ; C704.2 125.1,20.08 125.01,20.17 125.1,20.37 125.08,20.44 v2(125.1,20.49) ; C346.1 32.78,52.47 32.77,52.48 ; v2(33.21,23.73) 32.9,24.04 C329.2 ; v5(34.84,34.08) U101.H7 ; R118.2 v1(58.99,45.5) ; C130.2 52.77,47.73 52.71,47.66 ; U101.D12 v3(30.84,38.08) ; 13.08,27.85 13.08,28.11 ; v5(33.24,30.08) U101.F2 ; v5(33.24,33.28) U101.G6 ; v5(39.64,30.02) 39.64,30.08 U101.P3 ; C323.2 32.9,44.24 ; DS402.C v2(115.06,68.37) ; v5(34.04,36.48) U101.G10 ; C307.2 31.15,43.47 ; U101.K1 v5(36.44,28.48) ; U101.K1 v5(35.64,29.28) ; v5(31.64,32.48) U101.E6 ; U101.M2 v3(38.04,29.28) ; v5(35.64,38.88) U101.K14 v5(36.44,39.68) ; v5(35.64,38.88) U101.K13 ; C128.2 55.44,47.73 55.37,47.66 ; v2(115.71,52.34) U402.4 ; U101.F14 v3(32.44,39.68) ; U101.A7 28.56,33.68 v5(28.27,33.38) ; C136.2 R118.1 ; v5(33.24,34.88) U101.F8 ; v5(30.84,31.68) U101.C4 ; C308.2 38.48,43.47 ; v5(34.04,38.08) U101.G12 ; v5(30.04,34.88) U101.C9 ; v2(51.09,1.8) 51.28,1.99 U902.4 ; C316.2 31.41,24.68 ; v5(30.84,32.48) U101.D5 ; v5(30.84,34.08) U101.D7 ; 32.64,54.27 32.9,54.27 ; R711.1 116.24,20.73 v2(116.47,20.49) ; v3(30.84,30.88) U101.D4 ; v5(33.24,30.88) U101.G4 ; v5(31.64,33.28) U101.D6 ; U101.B14 v5(29.24,39.68) ; U101.D9 v5(30.84,35.68) ; v5(30.84,30.08) U101.D3 ; v5(33.24,36.48) U101.F10 ; v3(34.04,30.08) U101.G3 ; U101.N7 v3(38.84,33.28) ; v5(34.84,31.68) U101.H4 ; C425.2 100.84,40.81 v2(101.09,41.06) ; DS401.C v2(115.06,66.46) ; U101.A8 v5(28.44,34.88) ; U101.D11 v3(30.84,37.28) ; v5(32.44,33.28) U101.F6 ; C240.1 13.08,37.44 ; C242.1 14.04,27.83
  TOP w0.279: 26.67,41.82 C947.2
  TOP w0.305: 36.71,44.36 36.78,44.29 36.78,44.24 ; U703.6 v2(47.51,11.61) U703.PAD 48.02,10.09 U703.9 ; P101.2 96.53,38.97 R109.2 ; 32.9,54.27 C344.1 ; C706.2 v2(41.93,9.96) ; v1(134.02,59.31) 133.72,59 R801.1 ; R101.2 v4(28.26,41.84) ; U702.7 122.53,18.6 122.03,19.1 v2(121.93,19.1) ; R117.2 54.81,43.79 55.11,44.1 ; 32.9,55.16 C345.1 ; R114.2 52.39,36.43 52.85,35.97 ; R719.1 v2(55.9,14.91) ; R713.1 116.01,16.54 v2(116.14,16.66) 116.14,16.75 116.69,17.3 U702.4 ; v2(55.9,11.86) 54.75,11.86 ; R107.2 v2(93.52,44.94) ; 13.08,28.11 C243.2 ; 53.04,44.1 52.73,43.79 R115.2 ; v2(46.29,17.18) 46.31,17.17 46.31,17.08 46.29,17.07 R727.1 ; R113.2 60.01,36.43 ; R116.2 54.93,36.43 ; 54.75,8.81 v2(55.9,8.81) ; C948.2 26.48,41.75 v4(26.55,41.82) 26.67,41.82 ; U403.7 v2(122.74,50.47)
  TOP w0.394: R924.1 94.51,22.14 93.76,22.89 ; C431.1 91.77,59.53 v2(91.9,59.66) ; R918.1 81.31,10.25 79.67,10.25 v2(79.6,10.17) ; R105.2 91.46,35.49 91.44,35.47 ; C430.1 91.77,58.26 v2(91.9,58.39) ; 11.69,26.86 C208.2 ; C432.1 91.77,60.8 v2(91.9,60.93) ; C210.2 11.74,29.46 ; 11.14,43.28 C201.2 ; C437.1 89.03,63.81 v2(89.36,63.47) ; R919.1 82.43,15.63 v2(82.94,16.14) ; R928.1 90.65,5.74 v2(91.05,5.35) ; v2(33.07,14.15) C320.2 ; v2(48.39,17.18) 48.4,17.17 R725.1 ; P701.9 v2(55.12,66.02) ; C436.1 90.3,63.81 v2(90.63,63.47) ; R723.1 v4(50.48,17.18) ; C439.1 86.49,63.81 v2(86.82,63.47) ; v2(94.17,66.78) 94.17,67.3 C434.1 ; R715.2 54.75,8.81 ; v1(132.75,9.78) R112.2 ; C314.2 36.38,56.97 36.39,56.96 ; C438.1 87.76,63.81 v2(88.09,63.47) ; v2(36.61,54) C312.2 ; R914.2 86.08,22.24 86.73,22.89 ; C441.1 85.22,57.43 v2(85.22,57.85) ; 43.17,25.49 43.18,25.49 ; P701.5 v2(57.66,66.02) ; v2(49.05,67.11) 49.05,65.79 48.77,65.51 P701.19 ; P701.3 v2(58.93,66.02) ; C433.1 91.77,62.34 v2(91.9,62.2) ; C435.1 91.57,63.81 v2(91.9,63.47) ; C322.2 33.3,11.18 33.29,11.19 ; C351.1 36.77,12.93 36.83,12.87 ; R721.1 v4(52.58,17.18) ; C203.2 12.73,41.46 12.91,41.53 v4(12.96,41.63) ; C429.1 93.47,56.75 92.65,56.75 ; P701.15 v2(51.31,66.02) ; C444.1 85.22,64.91 v2(85.22,64.44) ; 54.75,11.86 R717.1 ; v2(86.63,3.9) R920.1 ; C428.1 92.55,56.65 92.65,56.75 ; v2(89.22,21.04) C903.1 ; 92.65,56.75 v2(92.65,56.81) ; C933.1 v2(59.45,0.9) ; C350.1 36.96,13.88
  TOP w0.508: 64.04,12.11 P904.2 ; P904.2 65.12,13.19 ; P904.2 65.12,11.03 ; P904.2 66.2,12.11 ; 32.9,65.32 32.9,66.71 ; 32.9,66.71 32.9,68.11 ; 32.9,66.71 34.29,66.71 ; 32.9,66.71 31.5,66.71 ; P102.16 52.4,49.7 ; P102.16 51.32,50.78 ; P102.16 51.32,48.62 ; P102.16 50.24,49.7 ; 37.98,65.32 37.98,66.71 ; 37.98,66.71 39.37,66.71 ; 37.98,66.71 37.98,68.11 ; 37.98,66.71 36.58,66.71 ; J304.2 38.61,1.44 ; J304.2 37.21,2.83 ; J304.2 35.82,1.44 ; 100.83,20.34 P905.2 ; P905.2 100.83,22.5 ; P905.2 99.75,21.42 ; P905.2 101.91,21.42 ; TP904.1 22.99,6.52 ; TP904.1 20.96,6.52 ; TP904.1 21.97,5.5 ; TP904.1 21.97,7.53 ; 32.9,60.24 J303.5 ; J303.5 32.9,63.03 ; J303.5 34.29,61.63 ; J303.5 31.5,61.63 ; P102.1 70.18,52.24 ; P102.1 68.02,52.24 ; P102.1 69.1,51.16 ; P102.1 69.1,53.32 ; J401.5 109.26,45.33 ; J401.5 106.72,45.33 ; J401.5 107.99,44.06 ; J401.5 107.99,46.6 ; TP902.1 97.92,4.1 ; TP902.1 97.92,2.07 ; TP902.1 96.9,3.09 ; 51.32,51.16 P102.15 ; P102.15 52.4,52.24 ; P102.15 51.32,53.32 ; P102.15 50.24,52.24 ; J304.4 32.13,7.91 ; J304.4 32.13,5.12 ; J304.4 33.53,6.52 ; P103.1 84.78,52.24 ; P103.1 83.7,53.32 ; P103.1 82.62,52.24 ; P103.1 83.7,51.16 ; 111.8,45.33 J401.4 ; J401.4 113.07,46.6 ; J401.4 114.34,45.33 ; J401.4 113.07,44.06 ; J304.3 37.21,7.91 ; J304.3 37.21,5.12 ; J304.3 38.61,6.52 ; J304.3 35.82,6.52 ; 72.46,38.85 P101.20 ; P101.20 73.54,39.93 ; P101.20 73.54,37.77 ; P101.20 74.62,38.85 ; J301.4 6.6,30.29 ; J301.4 3.18,29.28 ; J301.4 3.18,31.31 ; 33.53,1.44 32.13,1.44 32.13,2.83 ; P906.2 107.64,2.2 ; P906.2 106.56,1.12 ; P906.2 105.48,2.2 ; 57.28,17.44 TP602.1 58.3,18.46 ; 68.02,49.7 P102.2 ; P102.2 69.1,48.62 ; P102.2 69.1,50.78 ; P102.2 70.18,49.7 ; 63.98,18 P903.2 ; P903.2 65.06,19.08 ; P903.2 66.14,18 ; P101.1 97.48,41.39 ; P101.1 95.32,41.39 ; P101.1 96.4,42.47 ; J303.2 37.98,63.03 ; J303.2 36.58,61.63 ; J303.2 39.37,61.63 ; 6.6,38.79 J301.2 3.18,37.78 ; P101.2 97.48,38.85 ; P101.2 96.4,37.77 ; P101.2 95.32,38.85 ; P101.19 73.54,42.47 ; P101.19 74.62,41.39 ; P101.19 72.46,41.39 ; P101.19 73.54,40.31 ; J401.2 109.26,50.41 ; J401.2 107.99,49.14 ; J401.2 107.99,51.68 ; J401.2 106.72,50.41 ; 61.47,40.3 P104.1 ; P104.1 62.55,41.38 ; P104.1 61.47,42.46 ; 83.7,49.7 84.78,49.7 ; 83.7,49.7 83.7,50.78 ; 83.7,49.7 83.7,48.62 ; 83.7,49.7 82.62,49.7 ; 44.44,1.55 P907.2 ; P907.2 43.36,2.63 ; P907.2 44.44,3.71 ; 111.8,50.41 J401.3 ; J401.3 113.07,49.14 ; J401.3 113.07,51.68 ; J401.3 114.34,50.41 ; P104.2 62.55,38.84 ; P104.2 61.47,39.92 ; P104.2 61.47,37.76
  TOP w0.762: C932.2 v2(131.45,1.7)
  TOP w1.27: P904.2 65.38,12.37 68.02,12.37 C951.2
  L2_GND w0.508: P102.1 69.1,53.32 ; P102.1 68.02,52.24 ; P102.1 69.1,51.16 ; P102.1 70.18,52.24 ; 60.39,41.38 P104.1 ; P104.1 62.55,41.38 ; P104.1 61.47,40.3 ; P104.1 61.47,42.46 ; P905.2 100.83,22.5 ; P905.2 101.91,21.42 ; P905.2 100.83,20.34 ; P905.2 99.75,21.42 ; P904.2 65.12,13.19 ; P904.2 64.04,12.11 ; P904.2 65.12,11.03 ; P904.2 66.2,12.11 ; J304.3 37.21,7.91 ; J304.3 38.61,6.52 ; J304.3 35.82,6.52 ; J304.3 37.21,5.12 ; P907.2 45.52,2.63 ; P907.2 44.44,1.55 ; P907.2 44.44,3.71 ; P907.2 43.36,2.63 ; 51.32,51.16 P102.15 ; P102.15 52.4,52.24 ; P102.15 51.32,53.32 ; P102.15 50.24,52.24 ; P906.2 106.56,3.28 ; P906.2 107.64,2.2 ; P906.2 106.56,1.12 ; P906.2 105.48,2.2 ; 83.7,48.62 83.7,49.7 ; 83.7,49.7 82.62,49.7 ; 83.7,49.7 84.78,49.7 ; 83.7,49.7 83.7,50.78 ; 32.9,66.71 34.29,66.71 ; 32.9,66.71 32.9,68.11 ; 32.9,66.71 31.5,66.71 ; 32.9,66.71 32.9,65.32 ; 6.6,38.79 J301.2 3.18,37.78 ; TP602.1 59.31,17.44 ; TP602.1 57.28,17.44 ; TP602.1 58.3,16.42 ; TP602.1 58.3,18.46 ; P901.2 116.2,10.91 ; P901.2 117.53,9.57 ; P901.2 116.2,8.24 ; P901.2 114.86,9.57 ; 97.92,2.07 TP902.1 ; TP902.1 98.94,3.09 ; TP902.1 96.9,3.09 ; TP902.1 97.92,4.1 ; 69.1,48.62 P102.2 ; P102.2 68.02,49.7 ; P102.2 69.1,50.78 ; P102.2 70.18,49.7 ; 32.13,5.12 J304.4 ; J304.4 33.53,6.52 ; J304.4 32.13,7.91 ; P903.2 66.14,18 ; P903.2 65.06,16.92 ; P903.2 63.98,18 ; P903.2 65.06,19.08 ; 113.07,49.14 J401.3 ; J401.3 113.07,51.68 ; J401.3 111.8,50.41 ; J401.3 114.34,50.41 ; J401.4 114.34,45.33 ; J401.4 113.07,44.06 ; J401.4 111.8,45.33 ; J401.4 113.07,46.6 ; J301.4 6.6,30.29 ; J301.4 3.18,29.28 ; J301.4 3.18,31.31 ; 107.99,44.06 J401.5 ; J401.5 106.72,45.33 ; J401.5 109.26,45.33 ; J401.5 107.99,46.6 ; P101.1 96.4,42.47 ; P101.1 95.32,41.39 ; P101.1 96.4,40.31 ; P101.1 97.48,41.39 ; 36.58,61.63 J303.2 ; J303.2 39.37,61.63 ; J303.2 37.98,63.03 ; 72.46,38.85 P101.20 ; P101.20 73.54,39.93 ; P101.20 74.62,38.85 ; P101.20 73.54,37.77 ; P101.2 97.48,38.85 ; P101.2 95.32,38.85 ; P101.2 96.4,39.93 ; P101.2 96.4,37.77 ; 107.99,49.14 J401.2 ; J401.2 107.99,51.68 ; J401.2 106.72,50.41 ; J401.2 109.26,50.41 ; 72.46,41.39 P101.19 ; P101.19 74.62,41.39 ; P101.19 73.54,42.47 ; P101.19 73.54,40.31 ; 61.47,37.76 P104.2 ; P104.2 61.47,39.92 ; P104.2 62.55,38.84 ; P104.2 60.39,38.84 ; P103.1 84.78,52.24 ; P103.1 83.7,53.32 ; P103.1 83.7,51.16 ; P103.1 82.62,52.24 ; 35.82,1.44 J304.2 ; J304.2 37.21,2.83 ; J304.2 38.61,1.44 ; TP904.1 21.97,7.53 ; TP904.1 21.97,5.5 ; TP904.1 22.99,6.52 ; TP904.1 20.96,6.52 ; J303.5 34.29,61.63 ; J303.5 31.5,61.63 ; J303.5 32.9,60.24 ; J303.5 32.9,63.03 ; 51.32,48.62 P102.16 ; P102.16 52.4,49.7 ; P102.16 50.24,49.7 ; P102.16 51.32,50.78 ; 32.13,2.83 32.13,1.44 33.53,1.44 ; 36.58,66.71 37.98,66.71 ; 37.98,66.71 37.98,68.11 ; 37.98,66.71 37.98,65.32 ; 37.98,66.71 39.37,66.71
  L3_PWR w0.508: 69.1,51.16 P102.1 ; P102.1 69.1,53.32 ; P102.1 68.02,52.24 ; P102.1 70.18,52.24 ; P903.2 66.14,18 ; P903.2 63.98,18 ; P903.2 65.06,19.08 ; P903.2 65.06,16.92 ; P906.2 107.64,2.2 ; P906.2 106.56,1.12 ; P906.2 106.56,3.28 ; 97.48,38.85 P101.2 96.4,39.93 ; 31.5,66.71 32.9,66.71 ; 32.9,66.71 32.9,68.11 ; 32.9,66.71 32.9,65.32 ; 32.9,66.71 34.29,66.71 ; 106.72,45.33 J401.5 ; J401.5 107.99,44.06 ; J401.5 107.99,46.6 ; J401.5 109.26,45.33 ; J303.5 32.9,63.03 ; J303.5 34.29,61.63 ; J303.5 32.9,60.24 ; J303.5 31.5,61.63 ; 83.7,49.7 84.78,49.7 ; 83.7,49.7 83.7,50.78 ; 83.7,49.7 82.62,49.7 ; 83.7,49.7 83.7,48.62 ; 83.7,51.16 P103.1 ; P103.1 82.62,52.24 ; P103.1 84.78,52.24 ; P103.1 83.7,53.32 ; J303.2 37.98,63.03 ; J303.2 39.37,61.63 ; J303.2 36.58,61.63 ; TP904.1 22.99,6.52 ; TP904.1 20.96,6.52 ; TP904.1 21.97,5.5 ; 58.3,16.42 TP602.1 ; TP602.1 57.28,17.44 ; TP602.1 58.3,18.46 ; TP602.1 59.31,17.44 ; 106.72,50.41 J401.2 ; J401.2 107.99,49.14 ; J401.2 109.26,50.41 ; P907.2 44.44,3.71 ; P907.2 43.36,2.63 ; P907.2 45.52,2.63 ; P907.2 44.44,1.55 ; 6.6,38.79 J301.2 3.18,37.78 ; 96.4,40.31 P101.1 ; P101.1 95.32,41.39 ; P101.1 96.4,42.47 ; P101.1 97.48,41.39 ; 37.21,5.12 J304.3 ; J304.3 35.82,6.52 ; J304.3 38.61,6.52 ; P102.16 51.32,50.78 ; P102.16 51.32,48.62 ; P102.16 50.24,49.7 ; P102.16 52.4,49.7 ; 36.58,66.71 37.98,66.71 ; 37.98,66.71 37.98,68.11 ; 37.98,66.71 37.98,65.32 ; 37.98,66.71 39.37,66.71 ; P901.2 116.2,10.91 ; P901.2 114.86,9.57 ; P901.2 117.53,9.57 ; P901.2 116.2,8.24 ; P102.2 70.18,49.7 ; P102.2 69.1,50.78 ; P102.2 69.1,48.62 ; P102.2 68.02,49.7 ; 113.07,44.06 J401.4 ; J401.4 113.07,46.6 ; J401.4 114.34,45.33 ; J401.4 111.8,45.33 ; 65.12,11.03 P904.2 ; P904.2 65.12,13.19 ; P904.2 66.2,12.11 ; P904.2 64.04,12.11 ; P102.15 51.32,53.32 ; P102.15 50.24,52.24 ; P102.15 52.4,52.24 ; P102.15 51.32,51.16 ; J304.2 37.21,2.83 ; J304.2 35.82,1.44 ; J304.2 38.61,1.44 ; J301.4 3.18,31.31 ; J301.4 3.18,29.28 ; J301.4 6.6,30.29 ; J401.3 114.34,50.41 ; J401.3 113.07,49.14 ; J401.3 111.8,50.41 ; 32.13,5.12 J304.4 33.53,6.52 ; 33.53,1.44 32.13,1.44 32.13,2.83
  L4_GND w0.508: J301.4 3.18,31.31 ; J301.4 6.6,30.29 ; J301.4 3.18,29.28 ; P102.16 52.4,49.7 ; P102.16 51.32,48.62 ; P102.16 50.24,49.7 ; P102.16 51.32,50.78 ; P102.2 69.1,50.78 ; P102.2 68.02,49.7 ; P102.2 69.1,48.62 ; P102.2 70.18,49.7 ; P101.19 73.54,42.47 ; P101.19 74.62,41.39 ; P101.19 72.46,41.39 ; P101.19 73.54,40.31 ; P905.2 101.91,21.42 ; P905.2 99.75,21.42 ; P905.2 100.83,22.5 ; P905.2 100.83,20.34 ; P901.2 117.53,9.57 ; P901.2 114.86,9.57 ; P901.2 116.2,10.91 ; P901.2 116.2,8.24 ; J303.2 37.98,63.03 ; J303.2 39.37,61.63 ; J303.2 36.58,61.63 ; 63.98,18 P903.2 ; P903.2 66.14,18 ; P903.2 65.06,19.08 ; P903.2 65.06,16.92 ; P101.20 74.62,38.85 ; P101.20 72.46,38.85 ; P101.20 73.54,37.77 ; P101.20 73.54,39.93 ; P101.1 96.4,42.47 ; P101.1 95.32,41.39 ; P101.1 96.4,40.31 ; P101.1 97.48,41.39 ; 106.72,45.33 J401.5 ; J401.5 107.99,46.6 ; J401.5 107.99,44.06 ; J401.5 109.26,45.33 ; 97.92,2.07 TP902.1 ; TP902.1 97.92,4.1 ; TP902.1 98.94,3.09 ; TP902.1 96.9,3.09 ; P101.2 97.48,38.85 ; P101.2 95.32,38.85 ; P101.2 96.4,37.77 ; P101.2 96.4,39.93 ; P906.2 106.56,3.28 ; P906.2 106.56,1.12 ; P906.2 105.48,2.2 ; P906.2 107.64,2.2 ; TP904.1 22.99,6.52 ; TP904.1 21.97,7.53 ; TP904.1 21.97,5.5 ; TP904.1 20.96,6.52 ; 35.82,6.52 J304.3 ; J304.3 37.21,7.91 ; J304.3 38.61,6.52 ; J304.3 37.21,5.12 ; P103.1 84.78,52.24 ; P103.1 83.7,53.32 ; P103.1 83.7,51.16 ; P103.1 82.62,52.24 ; 3.18,37.78 J301.2 6.6,38.79 ; 32.9,60.24 J303.5 ; J303.5 32.9,63.03 ; J303.5 34.29,61.63 ; J303.5 31.5,61.63 ; J401.3 114.34,50.41 ; J401.3 113.07,51.68 ; J401.3 113.07,49.14 ; J401.3 111.8,50.41 ; 64.04,12.11 P904.2 ; P904.2 66.2,12.11 ; P904.2 65.12,11.03 ; P904.2 65.12,13.19 ; 82.62,49.7 83.7,49.7 ; 83.7,49.7 83.7,50.78 ; 83.7,49.7 84.78,49.7 ; 83.7,49.7 83.7,48.62 ; P104.1 61.47,42.46 ; P104.1 61.47,40.3 ; P104.1 60.39,41.38 ; P104.1 62.55,41.38 ; J304.2 37.21,2.83 ; J304.2 38.61,1.44 ; J304.2 35.82,1.44 ; 36.58,66.71 37.98,66.71 ; 37.98,66.71 37.98,65.32 ; 37.98,66.71 39.37,66.71 ; 37.98,66.71 37.98,68.11 ; 61.47,37.76 P104.2 ; P104.2 62.55,38.84 ; P104.2 60.39,38.84 ; P104.2 61.47,39.92 ; 32.9,66.71 34.29,66.71 ; 32.9,66.71 31.5,66.71 ; 32.9,66.71 32.9,65.32 ; 32.9,66.71 32.9,68.11 ; 106.72,50.41 J401.2 ; J401.2 109.26,50.41 ; J401.2 107.99,49.14 ; J401.2 107.99,51.68 ; J304.4 33.53,6.52 ; J304.4 32.13,7.91 ; J304.4 32.13,5.12 ; TP602.1 59.31,17.44 ; TP602.1 57.28,17.44 ; TP602.1 58.3,18.46 ; TP602.1 58.3,16.42 ; P102.1 70.18,52.24 ; P102.1 68.02,52.24 ; P102.1 69.1,51.16 ; P102.1 69.1,53.32 ; 50.24,52.24 P102.15 ; P102.15 51.32,53.32 ; P102.15 51.32,51.16 ; P102.15 52.4,52.24 ; 44.44,1.55 P907.2 ; P907.2 45.52,2.63 ; P907.2 43.36,2.63 ; P907.2 44.44,3.71 ; J401.4 114.34,45.33 ; J401.4 111.8,45.33 ; J401.4 113.07,46.6 ; J401.4 113.07,44.06 ; 32.13,2.83 32.13,1.44 33.53,1.44
  L5_SIG w0.508: 31.5,61.63 J303.5 ; J303.5 34.29,61.63 ; J303.5 32.9,60.24 ; J303.5 32.9,63.03 ; 111.8,50.41 J401.3 ; J401.3 113.07,49.14 ; J401.3 114.34,50.41 ; 60.39,41.38 P104.1 ; P104.1 62.55,41.38 ; P104.1 61.47,40.3 ; P104.1 61.47,42.46 ; TP904.1 21.97,7.53 ; TP904.1 22.99,6.52 ; TP904.1 20.96,6.52 ; TP904.1 21.97,5.5 ; P905.2 101.91,21.42 ; P905.2 100.83,20.34 ; P905.2 100.83,22.5 ; P905.2 99.75,21.42 ; 107.99,49.14 J401.2 ; J401.2 109.26,50.41 ; J401.2 106.72,50.41 ; 97.48,41.39 P101.1 95.32,41.39 ; 106.56,1.12 P906.2 ; P906.2 107.64,2.2 ; P906.2 106.56,3.28 ; P906.2 105.48,2.2 ; J301.4 6.6,30.29 ; J301.4 3.18,29.28 ; J301.4 3.18,31.31 ; 116.2,8.24 P901.2 ; P901.2 116.2,10.91 ; P901.2 114.86,9.57 ; P901.2 117.53,9.57 ; P904.2 65.12,13.19 ; P904.2 64.04,12.11 ; P904.2 66.2,12.11 ; 52.4,52.24 P102.15 50.24,52.24 ; P102.2 70.18,49.7 ; P102.2 69.1,50.78 ; P102.2 69.1,48.62 ; P102.2 68.02,49.7 ; J401.5 107.99,46.6 ; J401.5 106.72,45.33 ; J401.5 109.26,45.33 ; J401.5 107.99,44.06 ; 95.32,38.85 P101.2 97.48,38.85 ; J304.3 37.21,7.91 ; J304.3 38.61,6.52 ; J304.3 37.21,5.12 ; J304.3 35.82,6.52 ; 36.58,61.63 J303.2 ; J303.2 37.98,63.03 ; J303.2 39.37,61.63 ; 73.54,37.77 P101.20 ; P101.20 73.54,39.93 ; P101.20 72.46,38.85 ; P101.20 74.62,38.85 ; J401.4 113.07,46.6 ; J401.4 114.34,45.33 ; J401.4 113.07,44.06 ; J401.4 111.8,45.33 ; P102.1 70.18,52.24 ; P102.1 69.1,51.16 ; P102.1 68.02,52.24 ; P102.1 69.1,53.32 ; 32.9,65.32 32.9,66.71 ; 32.9,66.71 31.5,66.71 ; 32.9,66.71 32.9,68.11 ; 32.9,66.71 34.29,66.71 ; 96.9,3.09 TP902.1 ; TP902.1 98.94,3.09 ; TP902.1 97.92,2.07 ; TP902.1 97.92,4.1 ; J304.4 32.13,7.91 ; J304.4 32.13,5.12 ; J304.4 33.53,6.52 ; TP602.1 58.3,18.46 ; TP602.1 57.28,17.44 ; TP602.1 58.3,16.42 ; TP602.1 59.31,17.44 ; P103.1 83.7,53.32 ; P103.1 82.62,52.24 ; P103.1 84.78,52.24 ; P103.1 83.7,51.16 ; 66.14,18 P903.2 65.06,19.08 ; 73.54,40.31 P101.19 72.73,40.57 ; 83.7,49.7 84.78,49.7 ; 83.7,49.7 83.7,50.78 ; 83.7,49.7 82.62,49.7 ; P907.2 45.52,2.63 ; P907.2 44.44,3.71 ; P907.2 43.36,2.63 ; P907.2 44.44,1.55 ; 60.39,38.84 P104.2 ; P104.2 62.55,38.84 ; P104.2 61.47,39.92 ; 50.24,49.7 P102.16 52.4,49.7 ; 36.58,66.71 37.98,66.71 ; 37.98,66.71 39.37,66.71 ; 37.98,66.71 37.98,68.11 ; 37.98,66.71 37.98,65.32 ; J304.2 37.21,2.83 ; J304.2 35.82,1.44 ; J304.2 38.61,1.44 ; 6.6,38.79 J301.2 3.18,37.78 ; 33.53,1.44 32.13,1.44 32.13,2.83
  L6_GND w0.508: P102.1 70.18,52.24 ; P102.1 68.02,52.24 ; P102.1 69.1,51.16 ; P102.1 69.1,53.32 ; P101.2 96.4,39.93 ; P101.2 96.4,37.77 ; P101.2 95.32,38.85 ; P101.2 97.48,38.85 ; 21.97,5.5 TP904.1 ; TP904.1 20.96,6.52 ; TP904.1 21.97,7.53 ; TP904.1 22.99,6.52 ; P903.2 66.14,18 ; P903.2 65.06,19.08 ; P903.2 65.06,16.92 ; P903.2 63.98,18 ; 50.24,49.7 P102.16 ; P102.16 51.32,48.62 ; P102.16 52.4,49.7 ; P102.16 51.32,50.78 ; P101.19 74.62,41.39 ; P101.19 73.54,42.47 ; P101.19 73.54,40.31 ; P101.19 72.46,41.39 ; J304.4 32.13,7.91 ; J304.4 32.13,5.12 ; J304.4 33.53,6.52 ; 113.07,49.14 J401.3 ; J401.3 114.34,50.41 ; J401.3 113.07,51.68 ; J401.3 111.8,50.41 ; 96.4,40.31 P101.1 ; P101.1 96.4,42.47 ; P101.1 95.32,41.39 ; P101.1 97.48,41.39 ; 44.44,1.55 P907.2 ; P907.2 45.52,2.63 ; P907.2 44.44,3.71 ; P907.2 43.36,2.63 ; 6.6,38.79 J301.2 3.18,37.78 ; P904.2 65.12,13.19 ; P904.2 64.04,12.11 ; P904.2 65.12,11.03 ; P904.2 66.2,12.11 ; P901.2 116.2,10.91 ; P901.2 117.53,9.57 ; P901.2 116.2,8.24 ; P901.2 114.86,9.57 ; P905.2 101.91,21.42 ; P905.2 100.83,22.5 ; P905.2 99.75,21.42 ; P905.2 100.83,20.34 ; 72.46,38.85 P101.20 ; P101.20 74.62,38.85 ; P101.20 73.54,39.93 ; P101.20 73.54,37.77 ; P103.1 84.78,52.24 ; P103.1 83.7,51.16 ; P103.1 82.62,52.24 ; P103.1 83.7,53.32 ; 33.53,1.44 32.13,1.44 32.13,2.83 ; J303.5 34.29,61.63 ; J303.5 31.5,61.63 ; J303.5 32.9,60.24 ; J303.5 32.9,63.03 ; 61.47,37.76 P104.2 ; P104.2 62.55,38.84 ; P104.2 60.39,38.84 ; P104.2 61.47,39.92 ; 35.82,1.44 J304.2 ; J304.2 37.21,2.83 ; J304.2 38.61,1.44 ; 36.58,61.63 J303.2 ; J303.2 39.37,61.63 ; J303.2 37.98,63.03 ; 37.21,5.12 J304.3 ; J304.3 38.61,6.52 ; J304.3 37.21,7.91 ; J304.3 35.82,6.52 ; 3.18,29.28 J301.4 ; J301.4 6.6,30.29 ; J301.4 3.18,31.31 ; 31.5,66.71 32.9,66.71 ; 32.9,66.71 32.9,65.32 ; 32.9,66.71 32.9,68.11 ; 32.9,66.71 34.29,66.71 ; 106.72,50.41 J401.2 ; J401.2 109.26,50.41 ; J401.2 107.99,49.14 ; J401.2 107.99,51.68 ; TP602.1 58.3,18.46 ; TP602.1 58.3,16.42 ; TP602.1 57.28,17.44 ; TP602.1 59.31,17.44 ; P102.15 51.32,53.32 ; P102.15 51.32,51.16 ; P102.15 52.4,52.24 ; P102.15 50.24,52.24 ; 68.02,49.7 P102.2 ; P102.2 70.18,49.7 ; P102.2 69.1,50.78 ; P102.2 69.1,48.62 ; P906.2 106.56,3.28 ; P906.2 106.56,1.12 ; P906.2 105.48,2.2 ; P906.2 107.64,2.2 ; 60.39,41.38 P104.1 ; P104.1 61.47,42.46 ; P104.1 61.47,40.3 ; P104.1 62.55,41.38 ; 83.7,49.7 83.7,50.78 ; 83.7,49.7 83.7,48.62 ; 83.7,49.7 82.62,49.7 ; 83.7,49.7 84.78,49.7 ; J401.4 114.34,45.33 ; J401.4 111.8,45.33 ; J401.4 113.07,46.6 ; J401.4 113.07,44.06 ; 36.58,66.71 37.98,66.71 ; 37.98,66.71 37.98,65.32 ; 37.98,66.71 39.37,66.71 ; 37.98,66.71 37.98,68.11 ; J401.5 107.99,46.6 ; J401.5 106.72,45.33 ; J401.5 109.26,45.33 ; J401.5 107.99,44.06 ; 97.92,2.07 TP902.1 ; TP902.1 96.9,3.09 ; TP902.1 97.92,4.1 ; TP902.1 98.94,3.09
  L7_SIG w0.508: 3.18,29.28 J301.4 ; J301.4 6.6,30.29 ; J301.4 3.18,31.31 ; TP602.1 58.3,18.46 ; TP602.1 59.31,17.44 ; TP602.1 58.3,16.42 ; TP602.1 57.28,17.44 ; J303.2 37.98,63.03 ; J303.2 39.37,61.63 ; J303.2 36.58,61.63 ; P104.1 61.47,42.46 ; P104.1 60.39,41.38 ; P104.1 62.55,41.38 ; 96.4,40.31 P101.1 ; P101.1 97.48,41.39 ; P101.1 95.32,41.39 ; 3.18,37.78 J301.2 6.6,38.79 ; 63.98,18 P903.2 ; P903.2 66.14,18 ; P903.2 65.06,19.08 ; P903.2 65.06,16.92 ; P103.1 84.78,52.24 ; P103.1 83.7,51.16 ; P103.1 83.7,53.32 ; 50.24,49.7 P102.16 52.4,49.7 ; P906.2 106.56,3.28 ; P906.2 107.64,2.2 ; P906.2 105.48,2.2 ; P906.2 106.56,1.12 ; 68.02,52.24 P102.1 ; P102.1 69.1,53.32 ; P102.1 69.1,51.16 ; P102.1 70.18,52.24 ; 96.9,3.09 TP902.1 ; TP902.1 97.92,4.1 ; TP902.1 97.92,2.07 ; TP902.1 98.94,3.09 ; 31.5,61.63 J303.5 ; J303.5 32.9,63.03 ; J303.5 34.29,61.63 ; J303.5 32.9,60.24 ; 43.36,2.63 P907.2 ; P907.2 44.44,1.55 ; P907.2 45.52,2.63 ; P907.2 44.44,3.71 ; 37.21,5.12 J304.3 ; J304.3 37.21,7.91 ; J304.3 38.61,6.52 ; J304.3 35.82,6.52 ; 32.13,5.12 J304.4 ; J304.4 32.13,7.91 ; J304.4 33.53,6.52 ; P905.2 100.83,22.5 ; P905.2 100.83,20.34 ; P905.2 101.91,21.42 ; P905.2 99.75,21.42 ; 35.82,1.44 J304.2 ; J304.2 37.21,2.83 ; J304.2 38.61,1.44 ; 31.5,66.71 32.9,66.71 ; 32.9,66.71 32.9,65.32 ; 32.9,66.71 32.9,68.11 ; 32.9,66.71 34.29,66.71 ; TP904.1 21.97,7.53 ; TP904.1 22.99,6.52 ; TP904.1 21.97,5.5 ; TP904.1 20.96,6.52 ; 113.07,49.14 J401.3 ; J401.3 114.34,50.41 ; J401.3 111.8,50.41 ; 37.98,66.71 37.98,68.11 ; 37.98,66.71 37.98,65.32 ; 37.98,66.71 39.37,66.71 ; 37.98,66.71 36.58,66.71 ; 111.8,45.33 J401.4 ; J401.4 113.07,46.6 ; J401.4 114.34,45.33 ; 73.54,40.31 P101.19 ; P101.19 72.46,41.39 ; P101.19 74.62,41.39 ; 72.46,38.85 P101.20 ; P101.20 74.62,38.85 ; P101.20 73.54,37.77 ; P101.20 73.54,39.93 ; 116.2,8.24 P901.2 ; P901.2 117.53,9.57 ; P901.2 116.2,10.91 ; P901.2 114.86,9.57 ; 32.13,2.83 32.13,1.44 33.53,1.44 ; P904.2 65.12,13.19 ; P904.2 64.04,12.11 ; P904.2 66.2,12.11 ; P904.2 65.12,11.03 ; J401.5 107.99,46.6 ; J401.5 106.72,45.33 ; J401.5 109.26,45.33 ; P101.2 97.48,38.85 ; P101.2 96.4,39.93 ; P101.2 95.32,38.85 ; 107.99,49.14 J401.2 ; J401.2 109.26,50.41 ; J401.2 106.72,50.41 ; 52.4,52.24 P102.15 50.24,52.24 ; 60.39,38.84 P104.2 62.55,38.84 ; P102.2 70.18,49.7 ; P102.2 69.1,50.78 ; P102.2 68.02,49.7 ; 83.7,49.7 83.7,50.78 ; 83.7,49.7 84.78,49.7 ; 83.7,49.7 83.7,48.62
  L8_SIG w0.508: J401.5 109.26,45.33 ; J401.5 106.72,45.33 ; J401.5 107.99,44.06 ; J401.5 107.99,46.6 ; J401.4 114.34,45.33 ; J401.4 111.8,45.33 ; J401.4 113.07,44.06 ; J401.4 113.07,46.6 ; P101.19 74.62,41.39 ; P101.19 73.54,42.47 ; P101.19 72.46,41.39 ; 32.9,60.24 J303.5 ; J303.5 34.29,61.63 ; J303.5 32.9,63.03 ; J303.5 31.5,61.63 ; J304.2 38.61,1.44 ; J304.2 37.21,2.83 ; J304.2 35.82,1.44 ; 58.3,18.46 TP602.1 57.28,17.44 ; 68.02,52.24 P102.1 ; P102.1 69.1,51.16 ; P102.1 69.1,53.32 ; 107.99,49.14 J401.2 ; J401.2 106.72,50.41 ; J401.2 109.26,50.41 ; J401.2 107.99,51.68 ; 32.9,66.71 32.9,68.11 ; 32.9,66.71 31.5,66.71 ; 32.9,66.71 34.29,66.71 ; 32.9,66.71 32.9,65.32 ; P904.2 65.12,13.19 ; P904.2 66.2,12.11 ; P904.2 64.04,12.11 ; J304.4 32.13,7.91 ; J304.4 33.53,6.52 ; J304.4 32.13,5.12 ; 21.97,5.5 TP904.1 ; TP904.1 21.97,7.53 ; TP904.1 22.99,6.52 ; TP904.1 20.96,6.52 ; 111.8,50.41 J401.3 ; J401.3 114.34,50.41 ; J401.3 113.07,49.14 ; J401.3 113.07,51.68 ; 62.55,38.84 P104.2 61.47,37.76 ; J303.2 39.37,61.63 ; J303.2 36.58,61.63 ; J303.2 37.98,63.03 ; 96.4,40.31 P101.1 ; P101.1 96.4,42.47 ; P101.1 97.48,41.39 ; 72.46,38.85 P101.20 ; P101.20 74.62,38.85 ; P101.20 73.54,37.77 ; 83.7,48.62 83.7,49.7 ; 83.7,49.7 83.7,50.78 ; 83.7,49.7 84.78,49.7 ; 83.7,49.7 82.62,49.7 ; P103.1 84.78,52.24 ; P103.1 83.7,51.16 ; P103.1 82.62,52.24 ; J301.4 3.18,31.31 ; J301.4 3.18,29.28 ; J301.4 6.6,30.29 ; 37.21,5.12 J304.3 ; J304.3 35.82,6.52 ; J304.3 38.61,6.52 ; J304.3 37.21,7.91 ; 63.98,18 P903.2 ; P903.2 66.14,18 ; P903.2 65.06,19.08 ; 105.48,2.2 P906.2 107.64,2.2 ; 60.39,41.38 P104.1 62.55,41.38 ; 68.28,48.89 P102.2 69.1,50.78 ; 44.44,1.55 P907.2 ; P907.2 43.36,2.63 ; P907.2 45.52,2.63 ; P907.2 44.44,3.71 ; P905.2 100.83,22.5 ; P905.2 101.91,21.42 ; P905.2 99.75,21.42 ; 33.53,1.44 32.13,1.44 32.13,2.83 ; 37.98,65.32 37.98,66.71 ; 37.98,66.71 39.37,66.71 ; 37.98,66.71 37.98,68.11 ; 37.98,66.71 36.58,66.71 ; P101.2 97.48,38.85 ; P101.2 95.32,38.85 ; P101.2 96.4,39.93 ; P101.2 96.4,37.77 ; 96.9,3.09 TP902.1 ; TP902.1 98.94,3.09 ; TP902.1 97.92,4.1 ; 52.4,52.24 P102.15 50.24,52.24 ; 117.53,9.57 P901.2 116.2,8.24 ; 6.6,38.79 J301.2 3.18,37.78 ; 50.24,49.7 P102.16 52.4,49.7
  L9_GND w0.508: 43.36,2.63 P907.2 ; P907.2 44.44,1.55 ; P907.2 45.52,2.63 ; P907.2 44.44,3.71 ; P101.19 73.54,42.47 ; P101.19 73.54,40.31 ; P101.19 72.46,41.39 ; P101.19 74.62,41.39 ; 32.9,66.71 34.29,66.71 ; 32.9,66.71 31.5,66.71 ; 32.9,66.71 32.9,68.11 ; 32.9,66.71 32.9,65.32 ; P903.2 66.14,18 ; P903.2 65.06,16.92 ; P903.2 63.98,18 ; P903.2 65.06,19.08 ; 111.8,45.33 J401.4 ; J401.4 113.07,46.6 ; J401.4 113.07,44.06 ; J401.4 114.34,45.33 ; P102.16 52.4,49.7 ; P102.16 50.24,49.7 ; P102.16 51.32,50.78 ; P102.16 51.32,48.62 ; 32.9,60.24 J303.5 ; J303.5 32.9,63.03 ; J303.5 34.29,61.63 ; J303.5 31.5,61.63 ; 96.4,37.77 P101.2 ; P101.2 95.32,38.85 ; P101.2 96.4,39.93 ; P101.2 97.48,38.85 ; P901.2 117.53,9.57 ; P901.2 116.2,8.24 ; P901.2 114.86,9.57 ; P901.2 116.2,10.91 ; 32.13,2.83 32.13,1.44 33.53,1.44 ; TP902.1 97.92,4.1 ; TP902.1 96.9,3.09 ; TP902.1 97.92,2.07 ; TP902.1 98.94,3.09 ; 72.46,38.85 P101.20 ; P101.20 73.54,37.77 ; P101.20 73.54,39.93 ; P101.20 74.62,38.85 ; 106.56,1.12 P906.2 ; P906.2 107.64,2.2 ; P906.2 106.56,3.28 ; P906.2 105.48,2.2 ; TP904.1 21.97,7.53 ; TP904.1 22.99,6.52 ; TP904.1 20.96,6.52 ; TP904.1 21.97,5.5 ; 68.02,49.7 P102.2 ; P102.2 70.18,49.7 ; P102.2 69.1,50.78 ; P102.2 69.1,48.62 ; J303.2 39.37,61.63 ; J303.2 36.58,61.63 ; J303.2 37.98,63.03 ; 95.32,41.39 P101.1 ; P101.1 96.4,40.31 ; P101.1 96.4,42.47 ; P101.1 97.48,41.39 ; J304.2 38.61,1.44 ; J304.2 35.82,1.44 ; J304.2 37.21,2.83 ; P102.15 51.32,53.32 ; P102.15 52.4,52.24 ; P102.15 51.32,51.16 ; P102.15 50.24,52.24 ; 37.98,65.32 37.98,66.71 ; 37.98,66.71 36.58,66.71 ; 37.98,66.71 37.98,68.11 ; 37.98,66.71 39.37,66.71 ; P904.2 66.2,12.11 ; P904.2 65.12,13.19 ; P904.2 65.12,11.03 ; P904.2 64.04,12.11 ; 100.83,20.34 P905.2 ; P905.2 100.83,22.5 ; P905.2 101.91,21.42 ; P905.2 99.75,21.42 ; 57.28,17.44 TP602.1 ; TP602.1 58.3,18.46 ; TP602.1 58.3,16.42 ; TP602.1 59.31,17.44 ; 61.47,37.76 P104.2 ; P104.2 62.55,38.84 ; P104.2 60.39,38.84 ; P104.2 61.47,39.92 ; 3.18,37.78 J301.2 6.6,38.79 ; 106.72,50.41 J401.2 ; J401.2 107.99,49.14 ; J401.2 109.26,50.41 ; J401.2 107.99,51.68 ; 107.99,44.06 J401.5 ; J401.5 109.26,45.33 ; J401.5 106.72,45.33 ; J401.5 107.99,46.6 ; J301.4 6.6,30.29 ; J301.4 3.18,29.28 ; J301.4 3.18,31.31 ; 60.39,41.38 P104.1 ; P104.1 61.47,40.3 ; P104.1 61.47,42.46 ; P104.1 62.55,41.38 ; P103.1 84.78,52.24 ; P103.1 83.7,53.32 ; P103.1 82.62,52.24 ; P103.1 83.7,51.16 ; 69.1,51.16 P102.1 ; P102.1 70.18,52.24 ; P102.1 68.02,52.24 ; P102.1 69.1,53.32 ; 111.8,50.41 J401.3 ; J401.3 113.07,49.14 ; J401.3 114.34,50.41 ; J401.3 113.07,51.68 ; 83.7,49.7 84.78,49.7 ; 83.7,49.7 82.62,49.7 ; 83.7,49.7 83.7,50.78 ; 83.7,49.7 83.7,48.62 ; J304.4 32.13,7.91 ; J304.4 33.53,6.52 ; J304.4 32.13,5.12 ; J304.3 38.61,6.52 ; J304.3 37.21,5.12 ; J304.3 37.21,7.91 ; J304.3 35.82,6.52
  L10_SIG w0.127: 29.09,35.35 29.23,35.22 29.38,35.22 29.7,34.9 29.7,34.73 29.72,34.71
  L10_SIG w0.508: 65.06,16.92 P903.2 ; P903.2 65.06,19.08 ; P903.2 66.14,18 ; P903.2 63.98,18 ; P102.1 69.1,53.32 ; P102.1 68.02,52.24 ; P102.1 70.18,52.24 ; P102.1 69.1,51.16 ; P102.15 52.4,52.24 ; P102.15 50.24,52.24 ; P102.15 51.32,53.32 ; P102.15 51.32,51.16 ; P101.19 73.54,42.47 ; P101.19 73.54,40.31 ; P101.19 72.46,41.39 ; 43.36,2.63 P907.2 ; P907.2 45.52,2.63 ; P907.2 44.44,1.55 ; P907.2 44.44,3.71 ; 32.9,66.71 32.9,68.11 ; 32.9,66.71 34.29,66.71 ; 32.9,66.71 31.5,66.71 ; 32.9,66.71 32.9,65.32 ; 100.83,22.5 P905.2 99.75,21.42 ; 37.98,66.71 37.98,68.11 ; 37.98,66.71 37.98,65.32 ; 37.98,66.71 39.37,66.71 ; 37.98,66.71 36.58,66.71 ; 107.99,44.06 J401.5 ; J401.5 106.72,45.33 ; J401.5 109.26,45.33 ; J401.5 107.99,46.6 ; 31.5,61.63 J303.5 ; J303.5 34.29,61.63 ; J303.5 32.9,63.03 ; J303.5 32.9,60.24 ; 37.21,5.12 J304.3 ; J304.3 38.61,6.52 ; J304.3 35.82,6.52 ; J304.3 37.21,7.91 ; P901.2 117.53,9.57 ; P901.2 114.86,9.57 ; P901.2 116.2,8.24 ; P901.2 116.2,10.91 ; J301.4 6.6,30.29 ; J301.4 3.18,29.28 ; J301.4 3.18,31.31 ; 33.53,1.44 32.13,1.44 32.13,2.83 ; 107.99,49.14 J401.2 ; J401.2 109.26,50.41 ; J401.2 106.72,50.41 ; J401.2 107.99,51.68 ; P101.2 97.48,38.85 ; P101.2 95.32,38.85 ; P101.2 96.4,39.93 ; P101.2 96.4,37.77 ; 58.3,16.42 TP602.1 ; TP602.1 57.28,17.44 ; TP602.1 58.3,18.46 ; TP602.1 59.31,17.44 ; 72.46,38.85 P101.20 ; P101.20 73.54,37.77 ; P101.20 73.54,39.93 ; 83.7,51.16 P103.1 ; P103.1 84.78,52.24 ; P103.1 82.62,52.24 ; 21.97,5.5 TP904.1 ; TP904.1 21.97,7.53 ; TP904.1 20.96,6.52 ; TP904.1 22.99,6.52 ; 35.82,1.44 J304.2 ; J304.2 38.61,1.44 ; J304.2 37.21,2.83 ; 111.8,45.33 J401.4 ; J401.4 113.07,46.6 ; J401.4 114.34,45.33 ; J401.4 113.07,44.06 ; P102.2 70.18,49.7 ; P102.2 69.1,50.78 ; P102.2 69.1,48.62 ; P102.2 68.02,49.7 ; 61.47,40.3 P104.1 ; P104.1 62.55,41.38 ; P104.1 60.39,41.38 ; P101.1 97.48,41.39 ; P101.1 96.4,40.31 ; P101.1 96.4,42.47 ; P101.1 95.32,41.39 ; J401.3 113.07,51.68 ; J401.3 114.34,50.41 ; J401.3 113.07,49.14 ; J401.3 111.8,50.41 ; 32.13,5.12 J304.4 ; J304.4 33.53,6.52 ; J304.4 32.13,7.91 ; 3.18,37.78 J301.2 6.6,38.79 ; J303.2 39.37,61.63 ; J303.2 36.58,61.63 ; J303.2 37.98,63.03 ; 96.9,3.09 TP902.1 ; TP902.1 98.94,3.09 ; TP902.1 97.92,4.1 ; TP902.1 97.92,2.07 ; P104.2 61.47,39.92 ; P104.2 60.39,38.84 ; P104.2 62.55,38.84 ; P104.2 61.47,37.76 ; P102.16 51.32,50.78 ; P102.16 50.24,49.7 ; P102.16 52.4,49.7 ; P102.16 51.32,48.62 ; 105.48,2.2 P906.2 ; P906.2 107.64,2.2 ; P906.2 106.56,3.28 ; 83.7,50.78 83.7,49.7 84.78,49.7
  L11_GND w0.508: 61.47,37.76 P104.2 ; P104.2 62.55,38.84 ; P104.2 61.47,39.92 ; P104.2 60.39,38.84 ; J401.5 109.26,45.33 ; J401.5 107.99,46.6 ; J401.5 107.99,44.06 ; J401.5 106.72,45.33 ; 68.02,49.7 P102.2 ; P102.2 69.1,48.62 ; P102.2 70.18,49.7 ; P102.2 69.1,50.78 ; 105.48,2.2 P906.2 ; P906.2 106.56,1.12 ; P906.2 107.64,2.2 ; P906.2 106.56,3.28 ; J304.2 37.21,2.83 ; J304.2 35.82,1.44 ; J304.2 38.61,1.44 ; P102.1 70.18,52.24 ; P102.1 69.1,53.32 ; P102.1 69.1,51.16 ; P102.1 68.02,52.24 ; J401.4 113.07,46.6 ; J401.4 114.34,45.33 ; J401.4 113.07,44.06 ; J401.4 111.8,45.33 ; P907.2 45.52,2.63 ; P907.2 44.44,3.71 ; P907.2 44.44,1.55 ; P907.2 43.36,2.63 ; 32.13,2.83 32.13,1.44 33.53,1.44 ; J401.3 114.34,50.41 ; J401.3 113.07,51.68 ; J401.3 111.8,50.41 ; J401.3 113.07,49.14 ; 32.9,60.24 J303.5 ; J303.5 31.5,61.63 ; J303.5 34.29,61.63 ; J303.5 32.9,63.03 ; J304.4 33.53,6.52 ; J304.4 32.13,7.91 ; J304.4 32.13,5.12 ; 6.6,38.79 J301.2 3.18,37.78 ; J401.2 107.99,51.68 ; J401.2 109.26,50.41 ; J401.2 107.99,49.14 ; J401.2 106.72,50.41 ; 64.04,12.11 P904.2 ; P904.2 66.2,12.11 ; P904.2 65.12,13.19 ; P904.2 65.12,11.03 ; P101.19 74.62,41.39 ; P101.19 72.46,41.39 ; P101.19 73.54,40.31 ; P101.19 73.54,42.47 ; 83.7,51.16 P103.1 ; P103.1 84.78,52.24 ; P103.1 82.62,52.24 ; P103.1 83.7,53.32 ; 37.98,66.71 39.37,66.71 ; 37.98,66.71 37.98,65.32 ; 37.98,66.71 36.58,66.71 ; 37.98,66.71 37.98,68.11 ; 83.7,48.62 83.7,49.7 ; 83.7,49.7 84.78,49.7 ; 83.7,49.7 82.62,49.7 ; 83.7,49.7 83.7,50.78 ; 32.9,66.71 34.29,66.71 ; 32.9,66.71 31.5,66.71 ; 32.9,66.71 32.9,68.11 ; 32.9,66.71 32.9,65.32 ; P903.2 65.06,19.08 ; P903.2 65.06,16.92 ; P903.2 66.14,18 ; P903.2 63.98,18 ; 35.82,6.52 J304.3 ; J304.3 37.21,7.91 ; J304.3 38.61,6.52 ; J304.3 37.21,5.12 ; TP602.1 58.3,18.46 ; TP602.1 59.31,17.44 ; TP602.1 57.28,17.44 ; TP602.1 58.3,16.42 ; P102.15 52.4,52.24 ; P102.15 51.32,53.32 ; P102.15 50.24,52.24 ; P102.15 51.32,51.16 ; 97.92,2.07 TP902.1 ; TP902.1 96.9,3.09 ; TP902.1 98.94,3.09 ; TP902.1 97.92,4.1 ; 99.75,21.42 P905.2 ; P905.2 100.83,20.34 ; P905.2 101.91,21.42 ; P905.2 100.83,22.5 ; P101.1 97.48,41.39 ; P101.1 95.32,41.39 ; P101.1 96.4,42.47 ; P101.1 96.4,40.31 ; 60.39,41.38 P104.1 ; P104.1 61.47,40.3 ; P104.1 62.55,41.38 ; P104.1 61.47,42.46 ; 20.96,6.52 TP904.1 ; TP904.1 21.97,7.53 ; TP904.1 21.97,5.5 ; TP904.1 22.99,6.52 ; P901.2 116.2,10.91 ; P901.2 117.53,9.57 ; P901.2 114.86,9.57 ; P901.2 116.2,8.24 ; P101.2 96.4,39.93 ; P101.2 96.4,37.77 ; P101.2 95.32,38.85 ; P101.2 97.48,38.85 ; P102.16 52.4,49.7 ; P102.16 50.24,49.7 ; P102.16 51.32,48.62 ; P102.16 51.32,50.78 ; 3.18,29.28 J301.4 ; J301.4 3.18,31.31 ; J301.4 6.6,30.29 ; J303.2 39.37,61.63 ; J303.2 36.58,61.63 ; J303.2 37.98,63.03 ; P101.20 74.62,38.85 ; P101.20 73.54,37.77 ; P101.20 72.46,38.85 ; P101.20 73.54,39.93
  L12_PWR w0.508: 97.92,2.07 TP902.1 ; TP902.1 97.92,4.1 ; TP902.1 98.94,3.09 ; TP902.1 96.9,3.09 ; 35.82,1.44 J304.2 ; J304.2 38.61,1.44 ; J304.2 37.21,2.83 ; 113.07,49.14 J401.3 ; J401.3 111.8,50.41 ; J401.3 114.34,50.41 ; J401.3 113.07,51.68 ; 60.39,41.38 P104.1 ; P104.1 61.47,42.46 ; P104.1 61.47,40.3 ; P104.1 62.55,41.38 ; 3.18,37.78 J301.2 1.46,37.78 ; 31.5,66.71 32.9,66.71 ; 32.9,66.71 34.29,66.71 ; 32.9,66.71 32.9,65.32 ; 32.9,66.71 32.9,68.11 ; P101.20 73.54,39.93 ; P101.20 73.54,37.77 ; P101.20 72.46,38.85 ; P101.20 74.62,38.85 ; 36.58,66.71 37.98,66.71 ; 37.98,66.71 37.98,65.32 ; 37.98,66.71 39.37,66.71 ; 37.98,66.71 37.98,68.11 ; 106.72,45.33 J401.5 ; J401.5 107.99,46.6 ; J401.5 109.26,45.33 ; J401.5 107.99,44.06 ; 44.44,1.55 P907.2 ; P907.2 44.44,3.71 ; P907.2 43.36,2.63 ; 20.96,6.52 TP904.1 ; TP904.1 21.97,5.5 ; TP904.1 21.97,7.53 ; TP904.1 22.99,6.52 ; P103.1 83.7,53.32 ; P103.1 84.78,52.24 ; P103.1 82.62,52.24 ; P103.1 83.7,51.16 ; 35.82,6.52 J304.3 ; J304.3 37.21,5.12 ; J304.3 37.21,7.91 ; J304.3 38.61,6.52 ; 72.46,41.39 P101.19 ; P101.19 73.54,42.47 ; P101.19 73.54,40.31 ; P101.19 74.62,41.39 ; 66.14,18 P903.2 65.06,19.08 ; 99.75,21.42 P905.2 ; P905.2 101.91,21.42 ; P905.2 100.83,22.5 ; P905.2 100.83,20.34 ; 33.53,1.44 32.13,1.44 32.13,2.83 ; P102.1 69.1,53.32 ; P102.1 68.02,52.24 ; P102.1 69.1,51.16 ; P102.1 70.18,52.24 ; 69.1,48.62 P102.2 ; P102.2 70.18,49.7 ; P102.2 68.02,49.7 ; P102.2 69.1,50.78 ; 36.58,61.63 J303.2 ; J303.2 39.37,61.63 ; J303.2 37.98,63.03 ; 82.62,49.7 83.7,49.7 ; 83.7,49.7 84.78,49.7 ; 83.7,49.7 83.7,48.62 ; 83.7,49.7 83.7,50.78 ; 64.04,12.11 P904.2 65.12,13.19 ; 31.5,61.63 J303.5 ; J303.5 34.29,61.63 ; J303.5 32.9,63.03 ; J303.5 32.9,60.24 ; P102.16 52.4,49.7 ; P102.16 51.32,50.78 ; P102.16 51.32,48.62 ; P102.16 50.24,49.7 ; 60.39,38.84 P104.2 ; P104.2 61.47,37.76 ; P104.2 61.47,39.92 ; P104.2 62.55,38.84 ; P102.15 52.4,52.24 ; P102.15 51.32,53.32 ; P102.15 50.24,52.24 ; P102.15 51.32,51.16 ; 3.18,29.28 J301.4 3.18,31.31 ; J401.4 114.34,45.33 ; J401.4 111.8,45.33 ; J401.4 113.07,44.06 ; J401.4 113.07,46.6 ; 32.13,5.12 J304.4 ; J304.4 33.53,6.52 ; J304.4 32.13,7.91 ; 106.56,1.12 P906.2 ; P906.2 105.48,2.2 ; P906.2 107.64,2.2 ; 106.72,50.41 J401.2 ; J401.2 109.26,50.41 ; J401.2 107.99,51.68 ; J401.2 107.99,49.14
  L13_GND w0.508: 113.07,49.14 J401.3 ; J401.3 114.34,50.41 ; J401.3 113.07,51.68 ; J401.3 111.8,50.41 ; J304.2 37.21,2.83 ; J304.2 35.82,1.44 ; J304.2 38.61,1.44 ; 83.7,48.62 83.7,49.7 ; 83.7,49.7 83.7,50.78 ; 83.7,49.7 82.62,49.7 ; 83.7,49.7 84.78,49.7 ; 63.98,18 P903.2 ; P903.2 66.14,18 ; P903.2 65.06,19.08 ; P903.2 65.06,16.92 ; P101.20 73.54,39.93 ; P101.20 72.46,38.85 ; P101.20 74.62,38.85 ; P101.20 73.54,37.77 ; 50.24,52.24 P102.15 ; P102.15 52.4,52.24 ; P102.15 51.32,53.32 ; P102.15 51.32,51.16 ; 106.72,45.33 J401.5 ; J401.5 107.99,44.06 ; J401.5 109.26,45.33 ; J401.5 107.99,46.6 ; P101.1 96.4,42.47 ; P101.1 95.32,41.39 ; P101.1 97.48,41.39 ; P101.1 96.4,40.31 ; 106.56,1.12 P906.2 ; P906.2 105.48,2.2 ; P906.2 107.64,2.2 ; P906.2 106.56,3.28 ; TP904.1 21.97,7.53 ; TP904.1 20.96,6.52 ; TP904.1 22.99,6.52 ; TP904.1 21.97,5.5 ; J301.4 3.18,31.31 ; J301.4 6.6,30.29 ; J301.4 3.18,29.28 ; 95.32,38.85 P101.2 ; P101.2 97.48,38.85 ; P101.2 96.4,37.77 ; P101.2 96.4,39.93 ; 33.53,1.44 32.13,1.44 32.13,2.83 ; TP602.1 58.3,18.46 ; TP602.1 57.28,17.44 ; TP602.1 58.3,16.42 ; TP602.1 59.31,17.44 ; P905.2 100.83,22.5 ; P905.2 99.75,21.42 ; P905.2 101.91,21.42 ; P905.2 100.83,20.34 ; P102.16 52.4,49.7 ; P102.16 50.24,49.7 ; P102.16 51.32,50.78 ; P102.16 51.32,48.62 ; 114.86,9.57 P901.2 ; P901.2 116.2,8.24 ; P901.2 117.53,9.57 ; P901.2 116.2,10.91 ; 32.9,65.32 32.9,66.71 ; 32.9,66.71 34.29,66.71 ; 32.9,66.71 31.5,66.71 ; 32.9,66.71 32.9,68.11 ; J303.2 39.37,61.63 ; J303.2 36.58,61.63 ; J303.2 37.98,63.03 ; 35.82,6.52 J304.3 ; J304.3 37.21,5.12 ; J304.3 37.21,7.91 ; J304.3 38.61,6.52 ; P104.2 62.55,38.84 ; P104.2 61.47,37.76 ; P104.2 61.47,39.92 ; P104.2 60.39,38.84 ; 96.9,3.09 TP902.1 ; TP902.1 97.92,4.1 ; TP902.1 97.92,2.07 ; TP902.1 98.94,3.09 ; 83.7,51.16 P103.1 ; P103.1 84.78,52.24 ; P103.1 83.7,53.32 ; P103.1 82.62,52.24 ; 31.5,61.63 J303.5 ; J303.5 34.29,61.63 ; J303.5 32.9,60.24 ; J303.5 32.9,63.03 ; 64.04,12.11 P904.2 ; P904.2 66.2,12.11 ; P904.2 65.12,13.19 ; P904.2 65.12,11.03 ; P102.1 70.18,52.24 ; P102.1 69.1,53.32 ; P102.1 69.1,51.16 ; P102.1 68.02,52.24 ; P907.2 45.52,2.63 ; P907.2 43.36,2.63 ; P907.2 44.44,1.55 ; P907.2 44.44,3.71 ; 73.54,40.31 P101.19 ; P101.19 73.54,42.47 ; P101.19 74.62,41.39 ; P101.19 72.46,41.39 ; 111.8,45.33 J401.4 ; J401.4 113.07,44.06 ; J401.4 114.34,45.33 ; J401.4 113.07,46.6 ; 107.99,49.14 J401.2 ; J401.2 107.99,51.68 ; J401.2 106.72,50.41 ; J401.2 109.26,50.41 ; 37.98,66.71 39.37,66.71 ; 37.98,66.71 37.98,68.11 ; 37.98,66.71 36.58,66.71 ; 37.98,66.71 37.98,65.32 ; 60.39,41.38 P104.1 ; P104.1 62.55,41.38 ; P104.1 61.47,40.3 ; P104.1 61.47,42.46 ; P102.2 69.1,50.78 ; P102.2 68.02,49.7 ; P102.2 69.1,48.62 ; P102.2 70.18,49.7 ; 32.13,5.12 J304.4 ; J304.4 32.13,7.91 ; J304.4 33.53,6.52 ; 6.6,38.79 J301.2 3.18,37.78
  BOTTOM w0.203: C301.2 v7(17.33,33.36) ; 36.63,40.56 37.05,40.98 40.14,40.98 40.85,40.95 ; C303.2 v7(20.3,33.32) ; 30.87,30.27 30.62,30.52 30.62,31.19 30.72,31.29 30.72,31.44 30.85,31.57
  BOTTOM w0.254: v2(17.33,21.98) 17.41,21.98 17.41,21.92 17.43,21.93 T207.1 ; v6(38.88,30.13) 37.7,30.13 37.54,29.97 ; C613.2 29.9,26.89 ; 29.9,26.89 29.9,27.79 ; 29.9,26.89 29.9,26.23 29.5,25.83 v2(29.43,25.83) ; v2(85.46,13.17) 85.21,12.92 U901.30 ; v2(81.7,12.89) 81.42,12.61 Q901.4 82.1,12.17 v2(82.33,12.41) v2(82.33,13.17) ; U405.2 v2(105.47,66.77) ; C604.2 30.99,31.83 v5(30.84,31.68) ; v2(55.16,54.52) 54.49,53.85 C129.2 ; C122.2 67.19,48.31 68.59,49.7 P102.2 ; v2(91.9,58.39) 91.9,57 92.04,56.87 92.04,55.93 U401.4 ; 62.11,54.15 61.8,54.46 ; 62.11,54.15 C123.2 ; 62.11,54.15 62.11,54.18 v2(61.83,54.46) ; U401.9 89.54,57.26 89.36,57.44 v2(89.36,58.39) ; C126.2 59.57,48.31 60.21,48.94 ; U401.13 87.54,57.12 88.09,57.67 v2(88.09,58.39) ; C701.1 49.54,9.57 v2(49.55,9.58) ; C415.1 91.06,52.24 v2(90.55,51.73) 90.11,52.17 C414.1 ; 29.54,31.54 29.34,31.58 v5(29.24,31.68) 29.22,31.7 29.22,31.84 ; C605.2 31.22,29.9 31.12,30.01 ; v5(28.44,31.68) 28.46,31.69 28.46,31.86 ; v5(38.84,29.28) 38.83,29.28 C611.2 ; U901.11 92.07,10.92 v2(92.32,11.16) 92.06,11.42 U901.10 ; 62.75,48.94 62.75,48.59 C124.2 ; v2(66.91,54.46) 67.19,54.18 C121.2 ; C125.2 60.04,53.67 60.76,54.39 ; C133.2 77.6,53.76 ; 94.17,66.91 v2(94.17,66.78) ; 77.6,48.17 77.73,48.3 C134.2 ; U901.3 92.07,14.92 v2(92.32,15.16) 92.06,15.42 U901.2 ; C127.2 57.03,54.57 v2(57.18,54.73) ; 87.25,53 v2(87.19,53.06) C417.2 ; C132.2 80.14,48.3 ; C6.1 111.64,21.5 ; C247.1 17.24,20.26 ; C246.2 16.51,19.47 ; 20.5,49.86 20.49,49.85 C245.1 ; v5(30.84,30.08) 30.87,30.1 30.87,30.27 ; C622.2 29.47,34.84 ; C131.2 80.14,53.76
  BOTTOM w0.305: v6(41.42,34.46) 41.03,34.46 40.84,33.83 ; 28.88,40.81 C633.2 v1(29.85,40.81) ; 29.9,27.79 29.9,28.03 30.23,28.36 C615.2 30.24,28.74 v6(30.62,28.37) ; v2(43.56,62.27) 43.69,62.4 C135.2 ; T301.5 v7(22.23,32.26) ; C612.2 39.64,29.35 v5(39.64,29.28) ; Q901.1 v2(79.6,10.17) ; T301.2 v7(22.23,35.53) ; P801.C9 v1(140.37,50.42) ; v6(41,30.27) C610.2 41,29.31 ; C944.2 33.24,31.07 v5(33.24,30.88) ; C941.1 107.25,2.9 P906.2 105.86,2.9 C940.1
  BOTTOM w0.356: C244.2 v6(20.23,50.72)
  BOTTOM w0.381: v2(93.76,21.17) C912.1 R910.2 ; 86.73,22.89 87.45,22.17 C904.1 ; C901.2 83.81,22.51 84.19,22.89
  BOTTOM w0.394: P801.C20 P801.C21 v1(140.37,33.91) P801.D22 ; v1(140.36,58.01) 140.35,58.01 P801.D3 ; C906.1 v2(86.63,3.9) ; v1(136.56,38.99) P801.F18 P801.E17 ; v1(144.31,36.21) 143.92,35.81 P801.A20 P801.B19 ; P801.B35 v1(142.91,16.13) ; P801.K15 v1(131.48,42.8) ; P801.B26 v1(142.91,27.56) ; P801.J4 v1(132.75,56.77) ; v1(137.83,27.61) 137.88,27.61 P801.E26 ; P801.B10 v1(142.91,47.88) ; P801.J40 v1(132.75,9.78) ; P801.F33 v1(137.83,18.67) ; v1(140.37,50.42) P801.C8 ; P801.K6 v1(131.48,54.23) ; R913.2 88.63,20.46 v2(89.22,21.04) 89.7,20.56 C902.1 ; P801.B15 v1(142.91,41.53) ; P801.A36 v1(144.18,14.86) ; P801.E4 137.86,55.52 v1(137.85,55.52) 138.47,54.9 P801.E5 ; P801.F30 137.81,22.5 v1(137.88,22.5) ; P801.G26 v1(136.56,27.56) ; P801.J8 v1(132.75,51.69) ; P801.E1 v1(139.1,60.58) ; P801.A33 v1(144.18,18.67) ; v1(141.64,28.83) P801.C25 P801.C24 ; P801.K9 v1(131.52,49.18) ; P801.A16 143.67,40.89 144.37,40.2 v1(144.39,40.2) ; P801.B6 v1(142.91,52.96) P801.B7 ; P801.B3 142.89,56.79 v1(142.89,56.78) ; P801.A29 v1(144.18,23.75) ; P801.A32 v1(144.18,19.94) ; v1(135.29,60.58) P801.G1 ; v6(39.2,32.13) 39.2,32.85 C635.2 ; P801.H33 v1(135.29,18.67) ; P801.B39 v1(142.91,11.05) ; P801.A13 143.7,44.7 v1(144.38,44.03) ; v1(132.75,31.38) 132.75,31.37 P801.K24 ; P801.K18 P801.J17 v1(132.75,40.26) ; P801.B27 v1(142.91,26.29) ; P801.E20 v1(137.83,35.18) P801.F21 ; P801.E35 v1(139.1,16.13) ; P801.E29 v1(139.1,23.75) ; P801.J20 v1(134.02,35.18) P801.H21 ; P801.H24 v1(134.02,31.37) P801.J23 v1(132.75,32.64) ; P801.E38 v1(139.1,12.32) ; P801.G29 v1(136.56,23.75) ; P801.C17 P801.B18 v1(142.91,38.99) ; P801.A37 v1(144.18,13.59) ; P801.F9 v1(136.56,50.42) P801.G8 ; R414.2 v2(105.19,59.98) C408.2 ; P801.D2 v1(140.37,59.31) ; P801.K27 v1(131.48,26.29) ; P801.B31 v1(142.91,21.21) ; P801.A21 144.25,33.85 v1(145.91,33.85) ; v2(97.18,48.31) R404.1 ; P801.K30 v1(131.48,22.48) ; P801.E23 v1(137.83,32.64) ; v1(140.37,25.02) P801.D28 v1(139.1,26.29) ; P801.F15 v1(137.83,42.8) ; v1(137.83,28.83) P801.E26 ; P801.E26 P801.D25 ; P801.F36 v1(137.83,14.86) ; P801.D7 P801.D6 v1(139.1,54.23) ; v2(122.53,58.72) Y402.3 Y401.3 ; P801.H39 v1(135.29,11.05) ; P801.H9 v1(134.02,50.42) ; 15.58,52.75 15.3,52.62 C215.2 ; P801.B22 v1(142.91,32.64) P801.B23 ; P801.H3 v1(135.29,58.04) ; P801.D13 v1(139.1,45.34) ; P801.E8 v1(137.83,50.42) ; v2(127.14,60.52) C938.1 ; P801.J11 v1(134.05,46.58) P801.H12 ; P801.G32 v1(136.56,19.94) ; P801.G38 v1(136.56,12.32) ; P801.B11 v1(142.91,46.61) ; P905.2 100.54,21.14 C937.1 ; P801.D10 v1(139.1,47.88) P801.E11 ; P801.E40 v1(139.1,9.78) ; R402.1 v2(104.68,52.85) ; R442.2 v2(95.57,68.48) ; P801.C33 v1(141.64,18.67) ; P801.F24 v1(137.83,30.1) ; P801.G20 v1(136.56,36.45) ; P801.E14 v1(137.83,44.07) ; P801.H27 v1(134.02,27.56) ; P801.C32 v1(141.64,19.94) ; R403.2 v2(97.18,52.86) ; R906.2 v2(92.02,8.81) ; C217.2 v6(16.57,49.93) ; v1(144.38,45.3) 143.7,45.97 P801.A12 ; P801.C28 v1(141.64,25.02) ; P801.B30 v1(142.91,22.48) ; P801.A9 144.55,49.78 v1(145.22,49.11) ; P801.J35 v1(134.02,16.13) ; P801.J14 v1(134.02,42.8) P801.H15 ; v1(141.64,41.53) P801.C16 P801.D16 ; P801.G11 v1(136.56,46.61) ; P801.A25 144.01,29 v1(144.51,29) ; P801.H30 v1(134.02,22.48) ; P801.J32 v1(134.02,19.94) ; 18.62,41.64 v2(18.62,41.64) ; C908.1 91.09,22.17 91.81,22.89 ; v2(97.73,68.48) R441.1 ; P801.D39 v1(140.37,11.05) ; P801.F39 v1(137.83,11.05) ; P801.A17 143.67,39.62 144.37,38.93 v1(144.39,38.93) ; P801.A4 v1(144.18,55.5) ; P801.A40 v1(144.18,9.78) ; P801.K21 v1(132.75,33.91) ; P801.A1 v1(144.18,59.31) ; P801.C4 v1(141.64,55.5) P801.C5 ; P801.C40 v1(141.64,9.78) ; P801.G23 v1(136.56,32.64) ; C222.2 v6(16.77,14.33) ; C911.1 v2(86.6,20.99) ; P801.C36 v1(141.64,14.86) ; v2(96.64,68.48) R443.2 ; P801.G14 v1(136.56,44.07) ; v1(136.56,54.23) P801.G5 P801.G4 ; P801.F27 v1(137.83,26.29) ; P801.G17 v1(135.29,40.26) ; P801.H6 v1(134.02,54.23) ; P801.F6 v1(137.83,52.96) ; P801.A24 143.89,30.73 v1(144.54,30.09) ; P801.A8 143.66,51.05 v1(144.36,51.75) ; P801.F2 v1(136.56,58.04) ; P801.J26 v1(132.75,28.83) ; P801.D37 v1(140.37,13.59) ; P801.K2 v1(131.48,58.04) P801.K3 ; P801.D19 v1(140.37,36.45) ; P801.J5 v1(132.75,54.23) ; R409.1 v2(122.99,59.46) ; P801.A28 144.19,25.02 v1(144.28,25.02) ; R401.1 v2(105.81,51.08) ; P801.K39 v1(131.48,11.05) ; v2(90,3.9) C910.1 ; P801.H36 v1(134.02,14.86) ; C406.2 v2(123.8,62.81) ; P801.K36 v1(131.48,14.86) ; P801.J29 v1(134.02,23.75) ; P801.C12 P801.C13 v1(141.64,44.07) ; P801.G40 v1(136.56,9.78) ; P801.C1 v1(141.64,59.31) P801.B2 ; P801.C29 v1(141.64,23.75) ; P801.J1 v1(134.02,59.31) ; P801.G35 v1(136.56,17.4) ; P801.B34 v1(142.91,17.4) ; P801.K12 v1(131.48,45.34) ; P801.C38 v1(141.64,12.32) ; P801.E32 v1(139.1,19.94) ; P801.A5 v1(144.18,54.23) ; P801.K33 v1(131.48,18.67) ; P801.H18 v1(134.02,38.99) ; P801.F3 v1(137.83,56.77) ; P801.B14 v1(142.91,42.8) ; C407.1 v2(111,64.8) ; P801.J38 v1(134.02,12.32) ; P801.B38 v1(142.91,12.32) ; 84.04,5.28 C905.2 ; P801.F12 v1(137.83,45.34) ; C224.2 v6(18.88,16.54) C224.2
  BOTTOM w0.508: 73.54,40.31 P101.19 ; P101.19 73.54,42.47 ; P101.19 74.62,41.39 ; P101.19 72.46,41.39 ; P103.1 84.78,52.24 ; P103.1 83.7,51.16 ; P103.1 82.62,52.24 ; P103.1 83.7,53.32 ; P102.16 52.4,49.7 ; P102.16 51.32,48.62 ; P102.16 50.24,49.7 ; P102.16 51.32,50.78 ; P102.1 69.1,53.32 ; P102.1 69.1,51.16 ; P102.1 70.18,52.24 ; P102.1 68.02,52.24 ; P901.2 117.53,9.57 ; P901.2 116.2,8.24 ; P901.2 116.2,10.91 ; P901.2 114.86,9.57 ; 33.53,1.44 32.13,1.44 32.13,2.83 ; P101.20 73.54,39.93 ; P101.20 73.54,37.77 ; P101.20 74.62,38.85 ; P101.20 72.46,38.85 ; J303.2 39.37,61.63 ; J303.2 37.98,63.03 ; J303.2 36.58,61.63 ; 36.58,66.71 37.98,66.71 ; 37.98,66.71 37.98,68.11 ; 37.98,66.71 39.37,66.71 ; 37.98,66.71 37.98,65.32 ; 20.96,6.52 TP904.1 ; TP904.1 21.97,7.53 ; TP904.1 22.99,6.52 ; TP904.1 21.97,5.5 ; P102.15 52.4,52.24 ; P102.15 50.24,52.24 ; P102.15 51.32,53.32 ; P102.15 51.32,51.16 ; C616.2 35.37,31.42 v6(35.33,31.37) ; v5(28.27,33.38) 28.71,33.83 C627.2 ; 106.72,45.33 J401.5 ; J401.5 107.99,46.6 ; J401.5 109.26,45.33 ; C609.2 34.92,33.22 v6(35.19,33.48) ; 60.39,41.38 P104.1 62.55,41.38 ; J303.5 32.9,63.03 ; J303.5 34.29,61.63 ; J303.5 32.9,60.24 ; J303.5 31.5,61.63 ; 83.7,48.62 83.7,49.7 ; 83.7,49.7 83.7,50.78 ; 83.7,49.7 82.62,49.7 ; 83.7,49.7 84.78,49.7 ; C631.2 v2(29.34,42.78) ; 3.18,37.78 J301.2 6.6,38.79 ; P101.1 97.48,41.39 ; P101.1 96.4,42.47 ; P101.1 95.32,41.39 ; P101.1 96.4,40.31 ; v5(31.64,33.28) 31.61,33.25 C102.2 ; P102.2 69.1,50.78 ; P102.2 69.1,48.62 ; P102.2 70.18,49.7 ; P101.2 96.4,39.93 ; P101.2 97.48,38.85 ; P101.2 95.32,38.85 ; 64.04,12.11 P904.2 66.2,12.11 ; 111.8,45.33 J401.4 ; J401.4 113.07,46.6 ; J401.4 114.34,45.33 ; 113.07,49.14 J401.3 ; J401.3 114.34,50.41 ; J401.3 113.07,51.68 ; J401.3 111.8,50.41 ; J301.4 6.6,30.29 ; J301.4 3.18,31.31 ; J301.4 3.18,29.28 ; J304.2 37.21,2.83 ; J304.2 35.82,1.44 ; J304.2 38.61,1.44 ; v2(83.7,4.87) 83.7,4.94 84.04,5.28 v2(83.7,5.63) ; 98.94,3.09 TP902.1 96.9,3.09 ; 99.75,21.42 P905.2 100.83,22.5 ; 32.9,66.71 32.9,68.11 ; 32.9,66.71 34.29,66.71 ; 32.9,66.71 32.9,65.32 ; 32.9,66.71 31.5,66.71 ; P907.2 44.44,3.71 ; P907.2 45.52,2.63 ; P907.2 44.44,1.55 ; P907.2 43.36,2.63 ; J401.2 107.99,51.68 ; J401.2 109.26,50.41 ; J401.2 106.72,50.41 ; J401.2 107.99,49.14 ; 32.13,5.12 J304.4 ; J304.4 33.53,6.52 ; J304.4 32.13,7.91 ; 63.98,18 P903.2 65.06,19.08 ; 106.56,1.12 P906.2 107.64,2.2 ; J304.3 38.61,6.52 ; J304.3 37.21,5.12 ; J304.3 35.82,6.52 ; J304.3 37.21,7.91 ; v2(82.54,21.7) v2(82.54,21.02) 82.88,21.36 C901.2 ; v5(33.24,30.88) 33.46,30.65 C945.2 ; R932.2 71.83,19.41 v2(71.82,19.42) ; 60.39,38.84 P104.2 62.55,38.84
  BOTTOM w0.762: C640.2 65,12.23 P904.2 ; P907.2 44.74,2.94 C934.1
  BOTTOM w1.016: P903.2 64.67,18.39 C949.2
  vias: v1(139.1,44.07) v1(140.37,44.07) v1(140.37,38.99) v1(142.86,30.1) v1(145.35,31.03) v1(145.93,45.51) v1(145.92,44.16) v1(145.92,41.62) v1(145.92,39.08) v1(145.92,36.54) v1(146.06,46.57) v1(147.87,58.03) v1(147.87,52.95) v1(147.84,47.89) v1(147.87,32.65) v1(147.87,27.55) v1(147.87,22.47) v2(0.27,60.18) v2(0.28,56.67) v2(0.27,36.3) v2(0.28,32.8) v2(0.27,12.43) v2(0.28,8.92) v2(0.32,48.24) v2(0.32,44.73) v2(0.32,24.37) v2(0.32,20.86) v2(1.04,59.4) v2(1.04,57.44) v2(1.08,47.47) v2(1.08,45.5) v2(1.04,35.53) v2(1.04,33.56) v2(1.08,23.59) v2(1.08,21.62) v2(1.04,11.65) v2(1.04,9.69) v2(2.48,33.56) v2(2.62,35.5) v2(2.87,47.48) v2(2.79,23.6) v2(2.92,45.51) v2(3.18,21.62) v2(4.29,33.59) v2(4.61,47.25) v2(4.7,23.6) v2(4.8,45.23) v2(5.08,21.62) v2(5.16,35.5) v2(6.45,46.72) v2(6.58,44.57) v2(6.6,23.6) v2(6.83,33.59) v2(6.98,21.63) v2(7.3,37.06) v2(7.6,52.43) v2(7.61,51.06) v2(7.6,40.49) v2(7.61,39.12) v2(7.6,28.55) v2(7.61,27.18) v2(7.6,16.62) v2(7.61,15.24) v2(7.7,35.5) v2(8.05,49.92) v2(8.37,17.85) v2(8.41,24.18) v2(8.82,22.14) v2(9.16,52.47) v2(9.16,40.53) v2(9.18,36.66) v2(9.16,28.59) v2(9.16,16.66) v2(9.19,51.05) v2(9.19,39.11) v2(9.19,27.17) v2(9.19,15.23) v2(9.59,25.68) v2(9.82,29.23) v2(10,51.75) v2(10,39.81) v2(10.04,32.98) v2(10.06,31.5) v2(10,27.88) v2(10,15.94) v2(10.36,23.26) v2(10.43,48.06) v2(10.43,20.1) v2(10.59,54.26) v2(10.59,13.89) v2(11.4,24.86) v2(11.65,39.36) v2(11.63,37.92) v2(12.05,28.9) v2(12.05,27.46) v2(12.49,45.81) v2(12.49,22.34) v2(12.58,49.82) v2(12.65,52.02) v2(12.61,37.33) v2(12.61,36) v2(12.65,16.13) v2(13.03,39.04) v2(13.07,32.98) v2(13.08,27.6) v2(13.09,31.52) v2(13.53,37.38) v2(13.59,48.81) v2(14.23,48.17) v2(14.55,43.56) v2(14.55,24.59) v2(14.71,49.77) v2(14.71,18.38) v2(14.99,47.54) v2(15.88,46.52) v2(15.93,61.49) v2(15.89,59.93) v2(15.96,32.19) v2(15.89,9.16) v2(15.93,7.6) v2(16.61,59.09) v2(16.65,44.88) v2(16.6,41.31) v2(16.6,26.84) v2(16.61,10) v2(16.77,47.52) v2(16.77,20.63) v2(16.69,11.64) v2(17.15,31.13) v2(17.31,61.48) v2(17.32,59.9) v2(17.32,9.19) v2(17.31,7.61) v2(17.78,44.36) v2(17.73,25.95) v2(17.96,58.55) v2(18.38,32.93) v2(18.36,24.62) v2(18.33,14.22) v2(18.41,42.57) v2(18.4,31.56) v2(18.83,45.28) v2(18.83,22.88) v2(19.12,55.74) v2(19.58,44.04) v2(19.57,8.13) v2(19.97,16.79) v2(20.08,26.56) v2(20.29,52.92) v2(20.46,21.45) v2(20.66,32.19) v2(20.89,43.03) v2(20.89,25.12) v2(21.22,16.05) v2(21.21,10.7) v2(21.34,36.23) v2(21.41,61.52) v2(21.46,50.11) v2(21.66,20.62) v2(21.6,19.36) v2(22.57,58.7) v2(22.62,47.29) v2(22.85,31.6) v2(22.81,21.19) v2(22.84,13.23) v2(23.21,36.57) v2(23.24,21.93) v2(23.74,55.88) v2(23.79,44.47) v2(23.94,35.79) v2(24.27,46.62) v2(24.4,21.34) v2(24.46,15.83) v2(24.88,24.5) v2(24.9,53.07) v2(25.02,66.08) v2(25.15,22.9) v2(25.79,35.07) v2(25.91,26.2) v2(26.07,50.25) v2(26.16,66.08) v2(26.15,18.4) v2(26.69,60.4) v2(26.75,7.26) v2(27.01,57.85) v2(27.01,10.3) v2(27.28,54.82) v2(27.24,47.44) v2(27.31,66.08) v2(27.73,20.93) v2(27.95,59.93) v2(27.99,61.49) v2(28.05,53.17) v2(28.4,44.62) v2(28.67,59.09) v2(28.76,51.24) v2(29.37,61.48) v2(29.38,59.9) v2(29.38,23.53) v2(29.55,48.34) v2(29.75,9.16) v2(29.79,7.6) v2(29.89,50.57) v2(29.92,45.11) v2(29.96,21.63) v2(29.96,17.56) v2(30.46,10) v2(30.57,54.15) v2(30.59,13.99) v2(31.18,26.58) v2(31.17,9.19) v2(31.16,7.61) v2(31.19,59.64) v2(31.24,50.59) v2(31.24,45.12) v2(31.24,41.16) v2(31.2,21.63) v2(31.2,17.56) v2(31.45,46.52) v2(31.46,11.55) v2(31.51,47.54) v2(31.86,13.76) v2(31.92,41.17) v2(31.92,26.99) v2(32.17,51.56) v2(32.1,50.14) v2(32.47,22.49) v2(32.51,52.99) v2(32.64,49.26) v2(32.69,19.33) v2(33,20.53) v2(33.1,22.28) v2(33.13,3.96) v2(33.22,45.76) v2(33.22,44.43) v2(33.2,15.46) v2(33.42,8.86) v2(33.55,2.96) v2(33.61,18.89) v2(33.67,6.93) v2(33.59,5.04) v2(33.69,49.26) v2(33.96,63.82) v2(34.28,65.16) v2(34.44,63) v2(34.47,61.29) v2(34.46,59.33) v2(34.48,52.69) v2(34.51,57.75) v2(34.52,56.15) v2(34.52,54.45) v2(34.55,2.41) v2(34.65,18.89) v2(35.02,49.26) v2(35.15,13.7) v2(35.16,10.4) v2(35.19,15.46) v2(35.4,8.82) v2(35.56,65.74) v2(35.64,6.86) v2(35.67,5.15) v2(35.82,2.99) v2(35.99,18.89) v2(36.07,49.26) v2(36.15,4.33) v2(36.44,61.22) v2(36.44,59.29) v2(36.48,52.69) v2(36.46,44.43) v2(36.45,23.73) v2(36.46,22.28) v2(36.55,65.2) v2(36.51,63.11) v2(36.58,45.76) v2(36.7,50.96) v2(36.71,47.54) v2(36.98,64.19) v2(37.03,18.89) v2(37.16,15.16) v2(37.58,59.9) v2(37.58,18.01) v2(37.5,16.59) v2(37.71,56.86) v2(37.76,52.61) v2(37.75,26.99) v2(37.84,53.81) v2(37.85,48.67) v2(37.98,50.71) v2(38.04,47.66) v2(38.17,20.61) v2(38.23,44.62) v2(38.22,21.63) v2(38.43,41.16) v2(38.53,26.58) v2(38.64,7.12) v2(38.74,49.57) v2(38.78,10.17) v2(38.85,12.2) v2(38.99,15.24) v2(38.91,13.21) v2(39.04,16.26) v2(39.18,19.3) v2(39.23,20.61) v2(39.31,22.35) v2(39.4,25.57) v2(39.63,23.44) v2(40.04,42.96) v2(41.36,23.14) v2(41.54,11.74) v2(41.7,40.76) v2(41.83,61.5) v2(41.84,29.71) v2(41.96,58.46) v2(42.1,55.41) v2(42.23,52.37) v2(42.36,49.32) v2(42.49,46.28) v2(42.63,43.23) v2(42.71,34.64) v2(43.03,8.56) v2(43.16,11.61) v2(43.32,36.16) v2(43.3,14.65) v2(43.43,17.7) v2(43.56,20.74) v2(43.62,33.7) v2(43.7,29.46) v2(43.69,23.79) v2(43.85,41.07) v2(43.83,26.84) v2(44.27,43.89) v2(44.56,26.79) v2(44.89,49.89) v2(44.89,47.85) v2(44.89,45.82) v2(44.95,34.64) v2(45.07,51.91) v2(45.51,42.15) v2(45.64,36.14) v2(45.6,25.45) v2(45.82,38.86) v2(45.89,53.77) v2(46.05,34.02) v2(46.57,43.6) v2(46.98,49.21) v2(46.99,45.38) v2(47.06,51.19) v2(47,47.31) v2(47.28,55.25) v2(47.4,36.16) v2(47.51,10.59) v2(47.51,9.58) v2(47.74,37.79) v2(47.76,34.72) v2(47.88,52.94) v2(48.53,11.61) v2(48.53,10.59) v2(48.53,9.58) v2(49.08,56.2) v2(49.14,53.9) v2(49.16,34.01) v2(49.32,32.32) v2(49.48,0.44) v2(49.55,11.61) v2(49.55,10.59) v2(50.05,28.62) v2(50.61,34.95) v2(51.09,56.49) v2(51.1,54.33) v2(51.26,28.38) v2(51.6,33.92) v2(51.6,30.12) v2(51.66,25.5) v2(52.32,26.82) v2(53.12,56.55) v2(53.14,54.39) v2(53.37,35.93) v2(53.75,32.51) v2(53.88,3.77) v2(53.88,2.14) v2(54.32,33.92) v2(54.49,2.97) v2(54.87,35.98) v2(54.83,29.45) v2(55.06,25.59) v2(55,24.07) v2(55.15,56.68) v2(55.1,3.79) v2(55.1,2.14) v2(55.39,26.47) v2(55.53,32.37) v2(56.9,28.54) v2(57.17,56.89) v2(57.46,35.98) v2(57.41,34.08) v2(58.07,32.24) v2(58.1,30.47) v2(58.31,25.52) v2(58.44,23.27) v2(59.18,57.17) v2(59.13,28.88) v2(59.2,55.01) v2(59.33,34.11) v2(60,35.98) v2(60,32.24) v2(60.21,49.08) v2(60.44,26.63) v2(60.62,30.37) v2(61.18,57.52) v2(61.2,55.36) v2(61.58,22.89) v2(61.6,24.76) v2(61.87,34.11) v2(62.54,35.98) v2(62.54,32.24) v2(62.54,28.5) v2(62.92,48.81) v2(62.98,26.63) v2(63.17,57.95) v2(63.19,55.78) v2(63.16,30.37) v2(64.14,24.76) v2(64.12,22.89) v2(64.41,34.11) v2(65.08,35.98) v2(65.08,32.24) v2(65.08,28.5) v2(65.14,58.44) v2(65.16,56.28) v2(65.53,64.96) v2(65.53,62.02) v2(65.52,26.63) v2(65.7,30.37) v2(66.68,64.96) v2(66.68,62.02) v2(66.68,24.76) v2(66.66,22.89) v2(66.95,34.11) v2(67.09,59) v2(67.11,56.84) v2(67.62,35.98) v2(67.62,32.24) v2(67.62,28.5) v2(68.06,26.63) v2(68.24,30.37) v2(69.06,59.7) v2(69.08,57.54) v2(69.22,24.76) v2(69.2,22.89) v2(69.49,34.11) v2(70.16,32.24) v2(70.16,28.5) v2(70.6,26.63) v2(70.78,30.37) v2(70.8,36) v2(71,64.96) v2(71,62.02) v2(71.05,60.26) v2(71.06,58.09) v2(71,55.09) v2(71.41,11.42) v2(71.76,24.76) v2(71.74,22.89) v2(72.03,34.11) v2(72.14,64.96) v2(72.14,62.02) v2(72.14,58.04) v2(72.14,55.09) v2(72.7,32.24) v2(72.7,28.5) v2(72.97,35.99) v2(73.05,60.64) v2(73.06,58.48) v2(73.14,26.63) v2(73.19,11.42) v2(73.32,30.37) v2(74.05,46.19) v2(74.28,22.89) v2(74.3,24.76) v2(74.46,11.42) v2(74.57,34.11) v2(75.06,60.89) v2(75.08,58.72) v2(75.24,35.98) v2(75.24,32.24) v2(75.24,28.5) v2(75.31,64.96) v2(75.31,62.02) v2(75.68,26.63) v2(75.86,30.37) v2(76.11,11.42) v2(76.46,64.96) v2(76.46,62.02) v2(76.46,58.04) v2(76.46,55.09) v2(76.59,46.19) v2(76.84,24.76) v2(76.82,22.89) v2(77.11,34.11) v2(77.22,61.76) v2(77.38,11.42) v2(77.6,58.04) v2(77.6,55.09) v2(77.78,35.98) v2(77.78,32.24) v2(77.78,28.5) v2(78.22,26.63) v2(78.4,30.37) v2(79.38,24.76) v2(79.36,22.89) v2(79.65,34.11) v2(79.73,62.37) v2(79.73,57.48) v2(80.04,44.11) v2(80.32,35.98) v2(80.32,32.24) v2(80.32,28.5) v2(80.77,64.96) v2(80.77,62.02) v2(80.76,26.63) v2(80.94,30.37) v2(81.16,61.51) v2(81.16,58.33) v2(81.8,21.73) v2(81.83,20.99) v2(81.92,64.96) v2(81.92,24.76) v2(81.9,22.89) v2(82.19,34.11) v2(82.86,35.98) v2(82.86,32.24) v2(82.86,28.5) v2(83.3,26.63) v2(83.48,30.37) v2(84.46,24.76) v2(84.44,22.89) v2(84.73,34.11) v2(85.4,35.98) v2(85.4,32.24) v2(85.4,28.5) v2(85.46,15.71) v2(85.46,14.44) v2(85.46,11.9) v2(85.46,10.63) v2(85.84,26.63) v2(86.02,30.37) v2(86.73,15.71) v2(86.73,14.44) v2(86.73,13.17) v2(86.73,11.9) v2(86.73,10.63) v2(86.82,62.2) v2(86.82,60.93) v2(86.82,59.66) v2(86.82,58.39) v2(86.98,22.89) v2(87,24.76) v2(87.27,34.11) v2(87.94,35.98) v2(87.94,32.24) v2(87.94,28.5) v2(88,15.71) v2(88,14.44) v2(88,13.17) v2(88,11.9) v2(88,10.63) v2(88.09,62.2) v2(88.09,60.93) v2(88.09,59.66) v2(88.38,26.63) v2(88.56,30.37) v2(89.27,15.71) v2(89.27,14.44) v2(89.27,13.17) v2(89.27,11.9) v2(89.27,10.63) v2(89.36,62.2) v2(89.36,60.93) v2(89.36,59.66) v2(89.54,24.76) v2(89.52,22.89) v2(89.81,34.11) v2(90.48,32.24) v2(90.48,28.5) v2(90.43,11.98) v2(90.54,15.71) v2(90.54,14.44) v2(90.54,13.17) v2(90.54,10.63) v2(90.63,62.2) v2(90.63,60.93) v2(90.63,59.66) v2(90.63,58.39) v2(90.92,26.63) v2(91.1,30.37) v2(92.08,24.76) v2(92.06,22.89) v2(92.35,34.11) v2(93.02,32.24) v2(93.02,28.5) v2(93.48,35.99) v2(93.46,26.63) v2(93.64,30.37) v2(94.62,24.76) v2(94.6,22.89) v2(94.89,34.11) v2(95.56,32.24) v2(95.56,28.5) v2(95.64,35.96) v2(96,26.63) v2(96.18,30.37) v2(97.16,24.76) v2(97.14,22.89) v2(97.43,34.11) v2(98.1,32.24) v2(98.1,28.5) v2(98.32,35.99) v2(98.54,26.63) v2(99.02,22.89) v2(99.7,24.76) v2(99.97,30.37) v2(99.97,26.63) v2(100.19,34.12) v2(100.64,32.24) v2(100.64,28.5) v2(100.86,35.99) v2(101.56,22.89) v2(102.24,63.37) v2(102.24,57.27) v2(102.24,54.33) v2(102.24,24.76) v2(102.51,30.37) v2(102.51,26.63) v2(102.73,34.12) v2(102.91,12.56) v2(103.18,32.24) v2(103.18,28.5) v2(103.38,63.37) v2(103.38,54.33) v2(103.4,35.99) v2(103.67,12.56) v2(104.1,22.89) v2(104.43,12.56) v2(104.78,24.76) v2(105.05,30.37) v2(105.05,26.63) v2(105.27,34.12) v2(105.19,12.56) v2(105.72,32.24) v2(105.72,28.5) v2(105.94,35.99) v2(105.96,12.56) v2(106.72,12.56) v2(106.94,22.91) v2(107.07,24.81) v2(107.2,34.08) v2(107.45,30.4) v2(107.48,12.56) v2(107.7,63.37) v2(107.7,54.33) v2(107.71,26.59) v2(107.96,32.3) v2(107.96,28.49) v2(108.24,12.56) v2(108.84,63.37) v2(108.84,57.27) v2(108.84,54.33) v2(109.08,22.89) v2(109,12.56) v2(109.09,24.76) v2(109.37,34.11) v2(110.04,35.98) v2(110.04,32.24) v2(110.04,30.37) v2(110.04,28.5) v2(110.04,26.63) v2(111.63,24.76) v2(111.62,22.89) v2(112.14,21.5) v2(112.53,34.04) v2(112.57,30.22) v2(112.57,26.44) v2(112.89,32.06) v2(113.3,28.22) v2(113.93,23.16) v2(114.19,36.05) v2(114.26,24.72) v2(114.37,28.88) v2(114.47,32.67) v2(115.39,31.61) v2(115.77,27.63) v2(116.28,29.19) v2(116.64,25.3) v2(116.98,34.91) v2(117,27.18) v2(117.23,23.67) v2(117.41,37.13) v2(117.47,32.85) v2(117.56,56.21) v2(117.5,29) v2(118.04,31.28) v2(118.27,35.82) v2(118.37,22.65) v2(119.15,28.22) v2(119.4,36.08) v2(119.73,23.68) v2(119.86,34.1) v2(119.92,32.06) v2(120.1,38.78) v2(120.16,29.89) v2(121.17,24.88) v2(121.84,35.79) v2(121.94,28.9) v2(122.2,30.93) v2(122.43,24.24) v2(123.14,34.14) v2(123.38,30.22) v2(123.48,40.44) v2(123.54,38.75) v2(123.6,27.91) v2(124.04,23.35) v2(124.09,15.29) v2(124.38,31.79) v2(124.34,8.94) v2(124.41,21.26) v2(124.52,33.27) v2(124.6,56.26) v2(124.83,36) v2(124.95,54.76) v2(125.56,28.92) v2(126.06,20.3) v2(126.25,7.16) v2(126.37,31.78) v2(126.44,34.12) v2(126.63,0.43) v2(126.79,24.51) v2(127.05,30.26) v2(127.16,38.02) v2(127.19,40.27) v2(127.82,27.77) v2(127.94,33.26) v2(128.53,3.6) v2(128.68,29.44) v2(128.75,42.87) v2(129.04,32.21) v2(129.04,19.22) v2(129.26,23.69) v2(129.4,35.71) v2(129.55,37.25) v2(130.06,8.94) v2(130.13,30.45) v2(130.44,0.43) v2(130.91,28.48) v2(131.07,35.73) v2(131.07,33.45) v2(134.25,0.43) v2(138.06,6.78) v2(138.06,0.43) v2(141.87,6.78) v2(141.87,3.6) v2(141.87,0.43) v2(145.68,6.78) v2(145.68,3.6) v2(145.68,0.43) v3(41.03,36.04) v4(8.16,45.89) v4(8.19,43.54) v4(9.57,42.23) v4(9.7,44.78) v4(10.19,30.68) v4(10.8,40.94) v4(11.07,43.45) v4(11.88,31.55) v4(11.79,26.72) v4(11.95,43.99) v4(12.07,42.46) v4(13.06,29.61) v4(14.17,41.19) v4(14.17,31.7) v4(14.12,27.64) v4(14.8,27.29) v4(15.5,41.19) v4(15.5,31.7) v4(17.15,40.62) v4(17.15,39.58) v4(17.15,38.24) v4(17.15,37.19) v4(17.15,30.08) v4(17.15,28.75) v4(17.15,27.7) v4(18.68,26.88) v4(18.71,36.37) v4(19.41,41.23) v4(20.25,34.99) v4(20.33,37.73) v4(20.33,28.15) v4(20.84,40.85) v4(20.79,33.5) v4(21.28,31.35) v4(21.25,28.49) v4(21.41,37.99) v4(22.42,40.85) v4(22.96,38.05) v4(23.13,28.88) v4(23.41,31.16) v4(24.06,40.52) v4(24.27,37.99) v4(24.98,29.33) v4(25.03,31.81) v4(25.38,36.78) v4(25.69,39.53) v4(26.58,32.91) v4(26.62,35.38) v4(26.59,30.35) v4(26.98,38.12) v4(27.77,34.75) v4(27.7,31.13) v4(31.24,43.98) v4(31.83,19.48) v4(32.98,17.19) v4(33.16,12.67) v4(33.23,11) v4(35.16,12) v4(36.45,57.15) v4(36.52,55.48) v4(38.9,24.79) v4(47.96,27.83) v4(48.02,29.53) v4(81.92,62.02) v4(96.78,52.07) v4(96.78,49.13) v4(97.92,52.07) v4(97.92,49.13) v4(102.24,60.43) v4(102.24,52.07) v4(102.24,49.13) v4(103.38,60.43) v4(103.38,57.27) v4(103.38,52.07) v4(103.38,49.13) v4(107.7,60.43) v4(107.7,57.27) v4(108.84,60.43) v4(128.91,40.05) v4(130.44,38.4) v4(135.65,50.59) v4(136.41,57.2) v4(137.07,55.66) v4(137.55,58.47) v4(138.06,46.66) v4(138.69,57.45) v4(139.07,59.23) v4(140.6,31.16) v4(140.78,52.88) v4(141.11,40.18) v4(144.79,27.73) v4(144.92,58.47) v4(144.92,56.82) v4(144.92,22.65) v4(146.19,28.24) v5(41.03,36.04) v5(43.44,37.64) v5(43.95,39.42) v5(47,29.89) v5(47.38,32.43) v5(50.38,36.47) v5(51.85,31.52) v5(52.84,32.56) v5(54.67,30.88) v5(119.72,25.83) v5(124.11,25.88) v5(125.21,26.87) v5(126.25,21.94) v5(127.14,26.11) v5(128.74,20.9) v5(130.39,25.29) v5(131.4,20.21) v5(136.58,25.04) v5(136.69,26.34) v5(137.8,36.5) v5(139.07,25.07) v5(141.61,26.34) v5(144.31,31.75) v5(145.22,21.13) v5(145.3,26.44) v6(1.62,57.45) v6(2.35,59.39) v6(3.18,9.71) v6(3.45,11.64) v6(3.53,57.45) v6(4.25,59.39) v6(5.08,9.71) v6(5.35,11.64) v6(5.43,57.45) v6(6.16,59.39) v6(6.98,9.75) v6(7.25,11.71) v6(7.34,57.45) v6(8.06,59.38) v6(8.87,10) v6(8.9,33.57) v6(9.13,12.04) v6(9.24,57.35) v6(9.96,59.19) v6(10.04,35.48) v6(10.71,10.49) v6(10.94,12.63) v6(11.08,56.85) v6(11.57,33.57) v6(11.78,58.64) v6(12.48,11.21) v6(12.64,13.49) v6(12.75,55.94) v6(13.48,57.77) v6(14.17,54.67) v6(14.14,12.15) v6(14.2,14.58) v6(14.36,35.48) v6(14.36,33.57) v6(14.98,56.6) v6(15.28,53.12) v6(15.62,15.85) v6(15.66,13.29) v6(16.11,51.32) v6(16.25,55.18) v6(16.52,35.48) v6(16.61,17.16) v6(17.23,53.54) v6(17.28,48.72) v6(17.66,18.37) v6(17.76,15.48) v6(17.95,52.02) v6(18.01,47.01) v6(18.68,50.4) v6(19.63,22.3) v6(19.76,17.83) v6(19.85,45.86) v6(20.71,18.87) v6(21,46.53) v6(21.66,41.48) v6(22.34,26.74) v6(22.55,40.31) v6(23.28,27.45) v6(23.57,39.16) v6(23.53,23.57) v6(24.17,42.85) v6(24.09,28.49) v6(24.65,41.64) v6(24.68,38.15) v6(24.85,26.06) v6(25.08,29.51) v6(25.31,40.37) v6(25.66,27.12) v6(26.11,37.32) v6(26.36,39.54) v6(26.32,30.45) v6(26.53,27.96) v6(27.39,31.06) v6(27.57,39.07) v6(27.82,28.88) v6(30.6,38.6) v6(30.97,36.29) v6(31.07,37.56) v6(31.38,38.68) v6(31.96,39.75) v6(32.93,40.81) v6(33.13,37.28) v6(33.56,38.35) v6(34.02,41.65) v6(34.48,39.42) v6(35.26,42.29) v6(35.39,40.03) v6(35.88,27.86) v6(35.89,34.42) v6(36.08,36.95) v6(36.1,37.92) v6(36.36,40.48) v6(36.71,42.71) v6(36.84,32.35) v6(37.24,38.02) v6(37.78,36.83) v6(38.19,42.83) v6(38.72,34.96) v6(40.03,36.32) v6(41.02,25.19) v6(41.36,23.14) v6(41.87,28.88) v6(41.82,26.49) v6(42.55,40.81) v6(43.85,26.08) v6(43.93,25.32) v6(44.56,30.27) v6(44.71,41.57) v6(46.1,42.84) v6(46.87,44.49) v6(118.25,15.29) v6(121.8,11.6) v6(126.12,15.29) v6(126.12,11.6) v7(18.68,35.48) v7(18.81,33.57) v7(23.5,32.23) v7(25.03,35.1) v7(27.18,33.12) v7(27.8,36.95) v7(39.89,39.8)
